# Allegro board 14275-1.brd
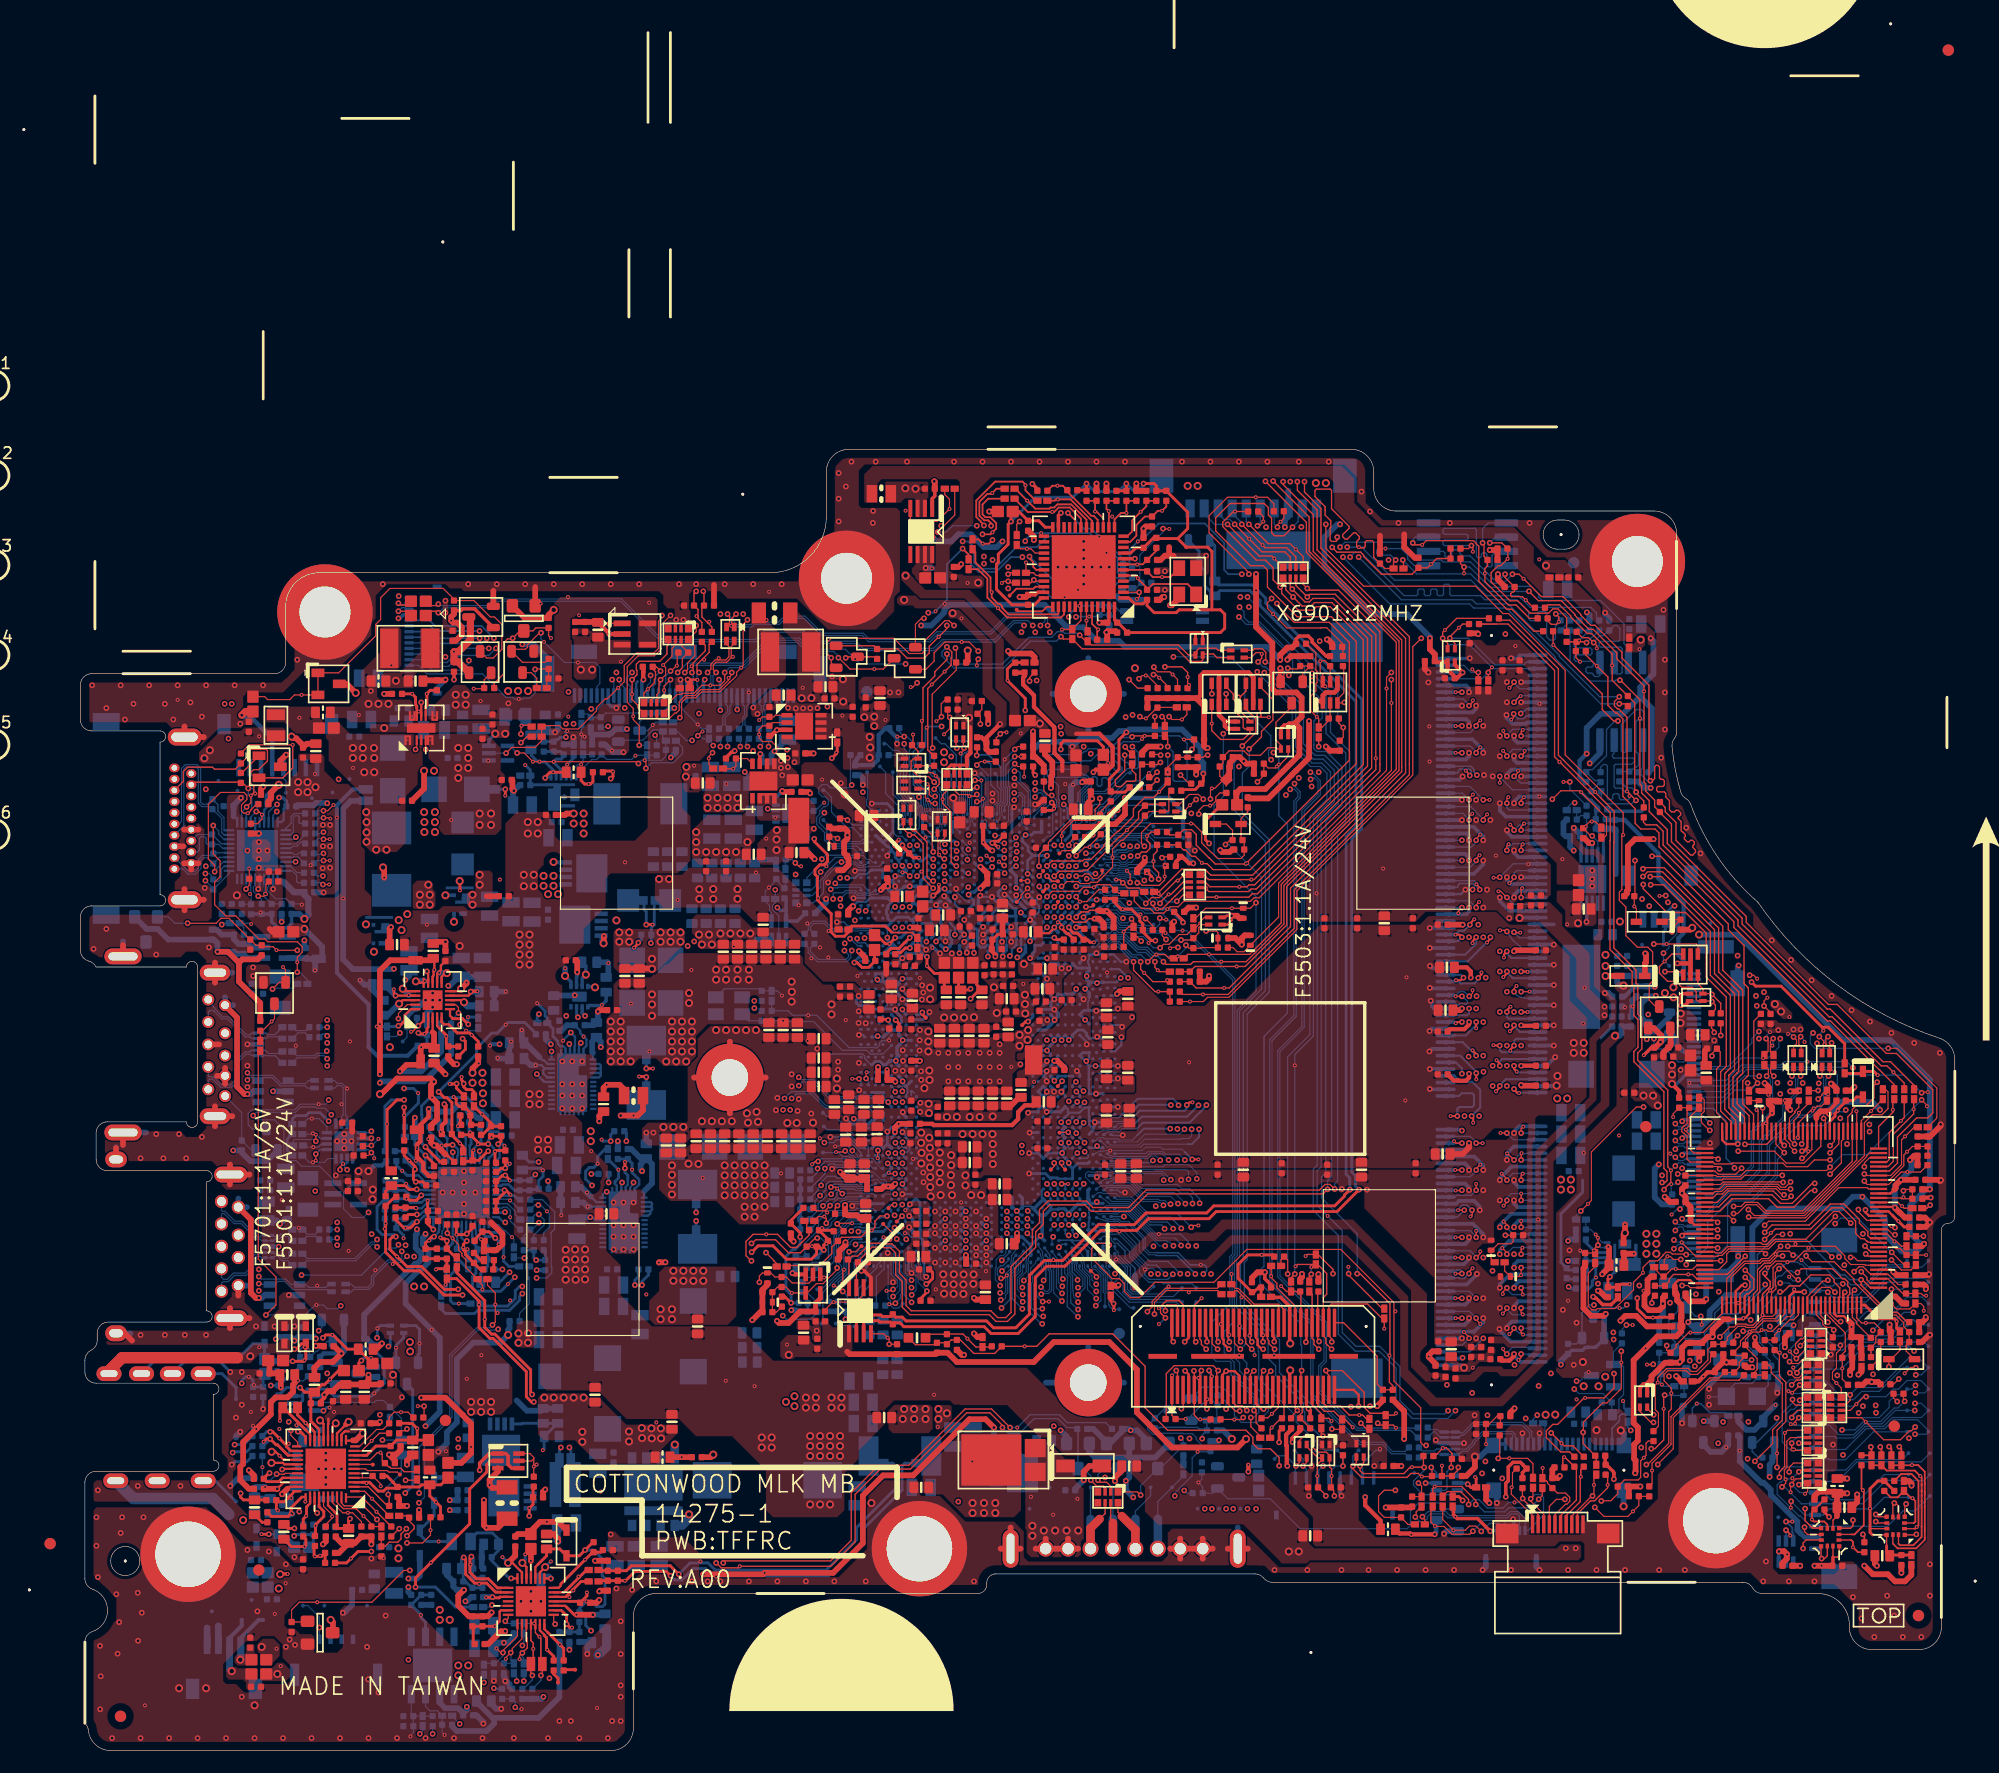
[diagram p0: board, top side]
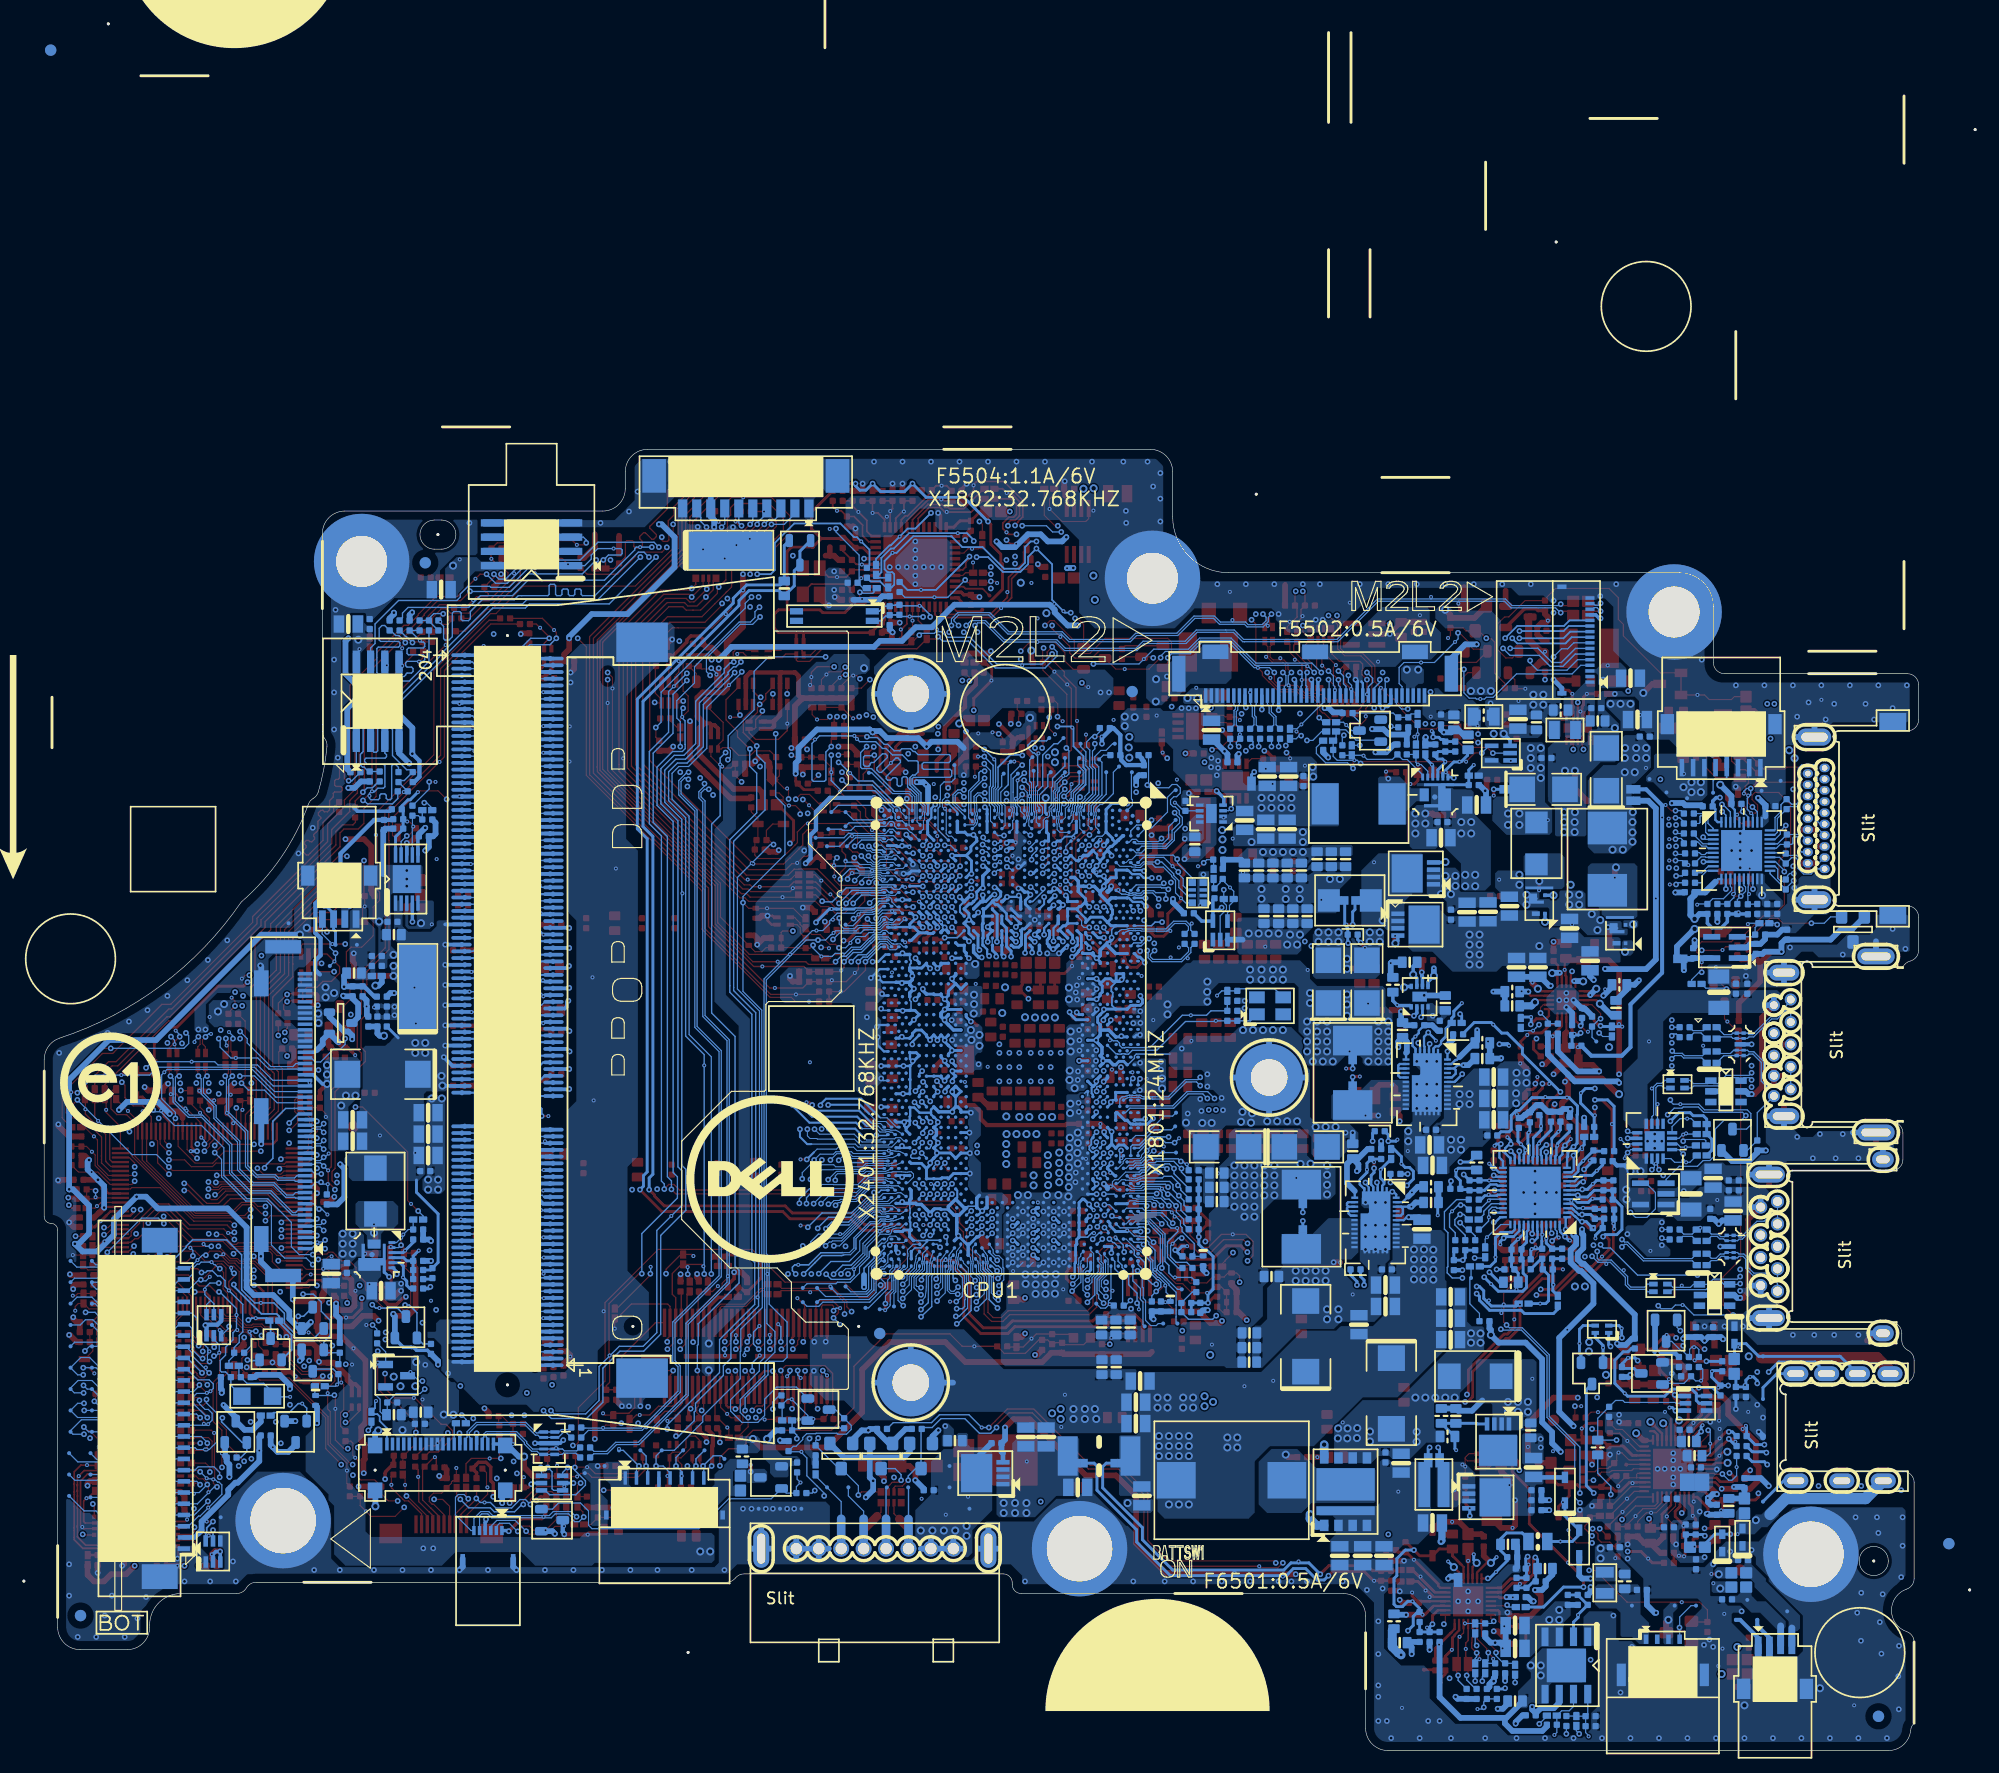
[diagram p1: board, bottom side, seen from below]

Outline 167.1 x 116 mm; copper layers: TOP, L2VCC, L3, L4, L5GND, L6, L7GND, BOTTOM. Coordinates in mm from the lower left corner of the outline.
Outline path: 0,95 0,91.9 arc(0.29,91.19) 1,90.9 7.1,90.9 arc(7.6,90.4) 7.1,89.9 7.1,76.3 arc(7.6,75.8) 7.1,75.3 1,75.3 arc(0.29,75.01) 0,74.3 0,71.35 arc(0.21,70.74) 0.75,70.38 arc(1.13,70.19) 1.4,69.85 9.45,69.85 arc(9.95,70.35) 10.45,69.85 10.45,56.05 arc(9.95,55.55) 9.45,56.05 2.4,56.05 arc(1.69,55.76) 1.4,55.05 1.4,52.7 arc(1.69,51.99) 2.4,51.7 11.25,51.7 arc(11.75,51.2) 11.25,50.7 11.25,39.2 arc(11.75,38.7) 11.25,38.2 2.5,38.2 arc(1.79,37.91) 1.5,37.2 1.5,36.58 arc(1.35,36.05) 0.95,35.68 arc(0.55,35.31) 0.4,34.79 0.4,33.75 arc(0.69,33.04) 1.4,32.75 11.85,32.75 arc(12.35,32.25) 11.85,31.75 11.85,25.9 arc(12.35,25.4) 11.85,24.9 1.4,24.9 arc(0.69,24.61) 0.4,23.9 0.4,15.34 arc(0.59,14.76) 1.07,14.39 arc(2.42,12.5) 1.07,10.61 arc(0.59,10.24) 0.4,9.66 0.4,2.44 arc(0.61,2.15) 0.71,1.81 arc(1.35,0.52) 2.7,0 47.3,0 arc(48.71,0.59) 49.3,2 49.3,12 arc(49.89,13.41) 51.3,14 80,14 arc(80.57,14.23) 80.8,14.8 80.8,14.95 arc(81.03,15.52) 81.6,15.75 104.71,15.75 arc(105.14,15.65) 105.49,15.37 arc(105.84,15.1) 106.27,15 148.21,15 arc(148.71,14.87) 149.07,14.5 arc(149.44,14.13) 149.94,14 154.9,14 arc(156.88,13.18) 157.7,11.2 157.7,11 arc(158.29,9.59) 159.7,9 163.9,9 arc(165.31,9.59) 165.9,11 165.9,46.4 arc(166.08,46.82) 166.5,47 arc(166.92,47.18) 167.1,47.6 167.1,61.61 arc(166.72,62.78) 165.72,63.51 arc(156.64,68.24) 149.55,75.63 arc(145.99,79.61) 143.55,84.36 arc(143.38,84.66) 143.12,84.88 arc(142.84,85.13) 142.67,85.46 arc(142.18,87.47) 141.89,89.52 arc(141.93,89.89) 142.1,90.23 arc(142.26,90.53) 142.31,90.87 arc(142.3,91.18) 142.3,91.5 142.3,108.5 arc(141.71,109.91) 140.3,110.5 117.3,110.5 arc(115.89,111.09) 115.3,112.5 115.3,114 arc(114.71,115.41) 113.3,116 68.5,116 arc(67.09,115.41) 66.5,114 66.5,110 arc(65.04,106.46) 61.5,105 21.3,105 arc(19.18,104.12) 18.3,102 18.3,97 arc(18.01,96.29) 17.3,96 1,96 arc(0.29,95.71) 0,95 ; 2.7,16.9 arc(4,18.2) 5.3,16.9 arc(4,15.6) 2.7,16.9 ; 6.7,17.5 arc(9.6,20.4) 12.5,17.5 arc(9.6,14.6) 6.7,17.5 ; 19.55,101.5 arc(21.8,103.75) 24.05,101.5 arc(21.8,99.25) 19.55,101.5 ; 56.3,60 arc(57.9,61.6) 59.5,60 arc(57.9,58.4) 56.3,60 ; 66.05,104.5 arc(68.3,106.75) 70.55,104.5 arc(68.3,102.25) 66.05,104.5 ; 71.9,18 arc(74.8,20.9) 77.7,18 arc(74.8,15.1) 71.9,18 ; 88.25,94.2 arc(89.85,95.8) 91.45,94.2 arc(89.85,92.6) 88.25,94.2 ; 88.25,32.8 arc(89.85,34.4) 91.45,32.8 arc(89.85,31.2) 88.25,32.8 ; 131.7,109.7 132.3,109.7 arc(133.6,108.4) 132.3,107.1 131.7,107.1 arc(130.4,108.4) 131.7,109.7 ; 136.55,106 arc(138.8,108.25) 141.05,106 arc(138.8,103.75) 136.55,106 ; 142.9,20.5 arc(145.8,23.4) 148.7,20.5 arc(145.8,17.6) 142.9,20.5

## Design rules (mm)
constraint set DEFAULT: min track width 0.127, pair gap 0.102
net group BOOST_MON: nets BOOST_MON I_BATT
net group CLK_PCI_LPC: nets CLK_PCI_LPC PCI_CLK_LPC0
net group CLK_PCI_LPC_MEC: nets CLK_PCI_LPC_MEC PCI_CLK_LPC1
net group DDR3_A_ODT10-MW: nets M_A_DIMA_ODT0 M_A_DIMA_ODT1
net group EDP_AUX: nets EDP_AUX EDP_AUX_DP
net group EDP_AUX#: nets EDP_AUX# EDP_AUX_DN
net group EDP_TX0: nets EDP_TX0 EDP_TX0_DP
net group EDP_TX0#: nets EDP_TX0# EDP_TX0_DN
net group EDP_TX1: nets EDP_TX1 EDP_TX1_DP
net group EDP_TX1#: nets EDP_TX1# EDP_TX1_DN
net group FAN_TACH: nets FAN_TACH1 FAN_TACH1_C
net group GND: nets EC_AGND MIC_GND
net group HDA_CODEC_RST#: nets HDA_CODEC_RST# HDA_RST#
net group HDA_CODEC_SDIN0: nets HDA_CODEC_SDIN0 HDA_SDIN0
net group HDA_CODEC_SYNC: nets HDA_CODEC_SYNC HDA_SYNC
net group I_SYS: nets I_SYS P_SYS
net group LCD_TST: nets LCD_TST LCD_TST_EN
net group LPC_LAD0: nets LPC_LAD0 LPC_LAD0_R
net group LPC_LAD1: nets LPC_LAD1 LPC_LAD1_R
net group LPC_LAD2: nets LPC_LAD2 LPC_LAD2_R
net group LPC_LAD3: nets LPC_LAD3 LPC_LAD3_R
net group LPC_LFRAME#: nets LPC_LFRAME# LPC_LFRAME#_R
net group PCIE_RX_CPU5-DIFF190: nets PCIE_RX_CPU_N5 PCIE_RX_CPU_P5
net group PCIE_TX_CPU_N5: nets PCIE_TX_CPU_N5 PCIE_TX_WLAN_N5
net group PCIE_TX_CPU_P5: nets PCIE_TX_CPU_P5 PCIE_TX_WLAN_P5
net group PWR_VCCGT_VSP: nets PWR_VCCGT_VSP VCCGT_SENSE
net group SPI_CLK_CPU: nets SPI_CLK_CPU SPI_CLK_ROM
net group SPI_CS_CPU_N0: nets SPI_CS_CPU_N0 SPI_CS_ROM_N0
net group SPI_HOLD_CPU: nets SPI_HOLD_CPU SPI_HOLD_ROM
net group SPI_SI_CPU: nets SPI_SI_CPU SPI_SI_ROM
net group SPI_SO_CPU: nets SPI_SO_CPU SPI_SO_ROM
net group SPI_WP_CPU: nets SPI_WP_CPU SPI_WP_ROM
net group USB20_DN0_C: nets USB20_DN0_C USB_PN0_R
net group USB20_DN1_C: nets USB20_DN1_C USB_CPU_PN1
net group USB20_DP0_C: nets USB20_DP0_C USB_PP0_R
net group USB20_DP1_C: nets USB20_DP1_C USB_CPU_PP1
net group USB30_RXDN1_C: nets USB30_RX_CPU_N1 USB30_RXDN1_C
net group USB30_RXDN2_C: nets USB30_RX_CPU_N2 USB30_RXDN2_C
net group USB30_RXDP1_C: nets USB30_RX_CPU_P1 USB30_RXDP1_C
net group USB30_RXDP2_C: nets USB30_RX_CPU_P2 USB30_RXDP2_C
net group USB_3+: nets USB_3+ USB_CPU_PP3
net group USB_3-: nets USB_3- USB_CPU_PN3
net group USB_CAMERA_N: nets USB_CAMERA_N USB_CPU_PN4
net group USB_CAMERA_P: nets USB_CAMERA_P USB_CPU_PP4
net group USB_CPU0-DIFF0: nets USB_CPU_PN0 USB_CPU_PP0
net group USB_CPU_PN2: nets USB_CPU_PN2 USB_CPU_PN2_C
net group USB_CPU_PN5: nets USB_CPU_PN5 USB_CPU_PN5_C
net group USB_CPU_PN6: nets USB_CPU_PN6 USB_PN6_TPNL
net group USB_CPU_PN7: nets USB_CPU_PN7 USB_CPU_PN7_C
net group USB_CPU_PP2: nets USB_CPU_PP2 USB_CPU_PP2_C
net group USB_CPU_PP5: nets USB_CPU_PP5 USB_CPU_PP5_C
net group USB_CPU_PP6: nets USB_CPU_PP6 USB_PP6_TPNL
net group USB_CPU_PP7: nets USB_CPU_PP7 USB_CPU_PP7_C
net group XTAL_48: nets RTC_X1 RTC_X2
net group AUDIO_20MIL: nets RING2 RING2_R RING2_R_C SLEEVE SLEEVE_R SLEEVE_R_C
net group AUDIO_BEEP_10MIL: nets AUD_HP1_JACK_L AUD_HP1_JACK_L1 AUD_HP1_JACK_R AUD_HP1_JACK_R1 AUD_PC_BEEP AUD_PC_BEEP_C AUD_PC_BEEP_R AUD_PORTA_L_R_B AUD_PORTA_R_R_B AUD_SENSE_A BEEP CBN CBP HDA_SPKR_R KBC_BEEP_R LINE1-L_C LINE1-L_R LINE1_L LINE1_R MICBIASB SENSE_PORTA SLEEVE_CTRL SPKR
net group AUDIO_OTHER_4MIL: nets CP_VNEG CP_VPOS LDO_AVDD LDO_VDD_CORE N18046859 VREFP
net group CFG_50-MW: nets CFG0 CFG1 CFG2 CFG3 CFG4 CFG5 CFG6 CFG7 CFG8 CFG9 CFG10 CFG11 CFG12 CFG13 CFG14 CFG15 CFG16 CFG17 CFG18 CFG19
net group CLK_50-MWS: nets SUSACK#_R SUSCLK SUSCLK_R
net group CODEC_BITCLK_R: nets CODEC_BITCLK_R HDA_BITCLK HDA_CODEC_BITCLK
net group CODEC_SDOUT_R: nets CODEC_SDOUT_R HDA_CODEC_SDOUT HDA_SDOUT
net group COMP_20MIL: nets CFG_RCOMP CPU_POPIRCOMP CSI2_COMP EDP_COMP EMMC_RCOMP PCH_POPIRCOMP SD_RCOMP SM_RCOMP_0 SM_RCOMP_1 SM_RCOMP_2 USBCOMP XCLK_BIASREF
net group CPU_50-MWS: nets CMP_VOUT1 H_PROCHOT# H_PROCHOT#_EC H_PROCHOT#_R PWR_CHG_PROCHOT#
net group DDR3_A_CMD_40-MW: nets M_A_A0 M_A_A1 M_A_A2 M_A_A3 M_A_A4 M_A_A5 M_A_A6 M_A_A7 M_A_A8 M_A_A9 M_A_A10 M_A_A11 M_A_A12 M_A_A13 M_A_A14 M_A_A15 M_A_BS0 M_A_BS1 M_A_BS2 M_A_CAS# M_A_RAS# M_A_WE#
net group DDR3_A_DATA_00_50-MW: nets M_A_DQ0 M_A_DQ1 M_A_DQ2 M_A_DQ3 M_A_DQ4 M_A_DQ5 M_A_DQ6 M_A_DQ7
net group DDR3_A_DATA_01_50-MW: nets M_A_DQ8 M_A_DQ9 M_A_DQ10 M_A_DQ11 M_A_DQ12 M_A_DQ13 M_A_DQ14 M_A_DQ15
net group DDR3_A_DATA_02_50-MW: nets M_A_DQ16 M_A_DQ17 M_A_DQ18 M_A_DQ19 M_A_DQ20 M_A_DQ21 M_A_DQ22 M_A_DQ23
net group DDR3_A_DATA_03_50-MW: nets M_A_DQ24 M_A_DQ25 M_A_DQ26 M_A_DQ27 M_A_DQ28 M_A_DQ29 M_A_DQ30 M_A_DQ31
net group DDR3_A_DATA_04_50-MW: nets M_A_DQ32 M_A_DQ33 M_A_DQ34 M_A_DQ35 M_A_DQ36 M_A_DQ37 M_A_DQ38 M_A_DQ39
net group DDR3_A_DATA_05_50-MW: nets M_A_DQ40 M_A_DQ41 M_A_DQ42 M_A_DQ43 M_A_DQ44 M_A_DQ45 M_A_DQ46 M_A_DQ47
net group DDR3_A_DATA_06_50-MW: nets M_A_DQ48 M_A_DQ49 M_A_DQ50 M_A_DQ51 M_A_DQ52 M_A_DQ53 M_A_DQ54 M_A_DQ55
net group DDR3_A_DATA_07_50-MW: nets M_A_DQ56 M_A_DQ57 M_A_DQ58 M_A_DQ59 M_A_DQ60 M_A_DQ61 M_A_DQ62 M_A_DQ63
net group DDR3_CKE_40-MW: nets M_A_CKE0 M_A_CKE1 M_A_CS#0 M_A_CS#1
net group JTAG-MW: nets EC5048_TX PCH_JTAG_TCK PCH_JTAG_TDI PCH_JTAG_TDO PCH_JTAG_TMS
net group KB: nets KSI0 KSI1 KSI2 KSI3 KSI4 KSI5 KSI6 KSI7 KSO0 KSO1 KSO2 KSO3 KSO4 KSO5 KSO6 KSO7 KSO8 KSO9 KSO10 KSO11 KSO12 KSO13 KSO14 KSO15 KSO16
net group LCD_BKLT: nets BKLT_CTRL L_BKLT_CTRL LCD_BRIGHTNESS
net group LED: nets BAT1_LED# BAT2_LED# BATT_WHITE_LED# CAP_LED# CAP_LED_R# CHG_AMBER_LED#
net group LED_20MIL: nets CAP_LED CAP_LED#_R CAP_LED_Q
net group LPC-MW: nets LPC_FRAME#_DEBUG LPC_LAD0_C LPC_LAD1_C LPC_LAD2_C LPC_LAD3_C SERIRQ
net group OTHER_4MIL-MWS: nets +3VLP A5_TP A67_TP A70_TP AC_PRESENT AD+_G_1 AD_IA ALS_INT# ALS_INT#_HUB AUX_EN_WOWL AV1_TP AV71_TP B71_TP BA1_TP BA2_TP BA71_TP BB67_TP BB70_TP BKLGT_PWM BLON_OUT BLON_OUT_C BOARD_ID BT_RADIO_DIS# C1_TP CAM_MIC_CBL_DET# CFG CLKREQ_PCIE#1 CLKREQ_PCIE#2 CLKREQ_PCIE#3 CLKREQ_PCIE#4 CLKREQ_PCIE#5 CLKREQ_PEG#0 CLKRUN# CLKRUN#_R CPU_DP1_HPD CTL1 CTL2 CTL3 DBC_EN_R DBC_PANEL_EN DCIN_EN DDCBUF DDR0_PAR DDR1_PAR E51_TXD_R E71_TP EAPD# EC_MUTE# EC_WAKE# EDP_DISP_UTIL EDP_HPD EDP_HPD_CONN EQ FAN1_PWM FAN_PWM1_C GPD2/LAN_WAKE# GPD11/LANPHYPC GPP_B2/VRALERT# GPP_B4/CPU_GP3 GPP_B18/GSPI0_MOSI GPP_B22 GPP_B23/SML1ALERT# GPP_C2/SMBALERT# GPP_C5/SML0ALERT# GPP_E0/SATAXPCIE0/SATAGP0 GPP_E1/SATAXPCIE1/SATAGP1 GPP_E2/SATAXPCIE2/SATAGP2 GPP_E3/CPU_GP0 H_CATERR# HDD_DEVSLP HDD_DEVSLP_R HDD_EN_PCH HDMI_EC_DET# HDMI_EC_DET#_C HOME_BTN# HOME_BTN#_C HOST_DEBUG_TX HPD_HDMI_CON HPD_HDMI_CON_C HSIOPC_R HSYNC_LCD HSYNC_R HSYNC_TPNL I_ADP ICSP_CLK_R ICSP_CLR ICSP_DATA_R ICSP_MCLR_R ILIM_HI ILIM_LO ILIM_SEL INT_TP# ISET ITP_PMODE JTAG_CLK JTAG_PU JTAG_RST# JTAG_TDO KB_CLOSE#_2 KB_DISABLE KB_DISABLE_HUB KBC_PWRBTN# L_BKLT_EN L_BKLT_EN_EC LCD_TST_C LID_CL_SIO# ME_FWP_EC MSM# MUTE_CTRL PANEL_SIZE1 PBAT_PRES1# PBAT_PRES# PCH_ALW_ON PCH_BATLOW# PCH_PLTRST#_EC PCH_THERMTRIP# PCH_WAKE# PIRQA# PLT_RST# PME# POWER_SW_IN# PRE PROC_SELECT# PS_ID PS_ID_R2 PSYS PWR_5V_VCLK PWR_CHG_ACOK PWR_CHG_IADP PWR_CHG_IBAT PWR_CHG_PMON RESET_OUT# REXT RTC_DET# SA0_DIMA SA1_DIMA SATA_ACT# SIO_EXT_SCI# SIO_EXT_SCI#_R SIO_EXT_SMI# SIO_EXT_SMI#_R SIO_PWRBTN# SKTOCC# SM_INTRUDER# SPDIF_TP SPKR_MUTE_TP SYS_PRES1# TOUCHPAD_INTR# TP_EN# TP_PMODE_XDP_RST_R_N U4006_CT USB_OC0# USB_OC1# USB_OC2# USB_OC3# USB_UART_SEL_D9 USBCHARGER_CB0 USBDET_CON# USBDET_CON#_R VCREF0 VOL_DOWN# VOL_UP# VR_EN VR_RDY WIFI_RF_EN ZVM#
net group PEC_50-MWS: nets H_PECI PCH_PLTRST# PECI_EC
net group PLATFORM-MWS: nets 1D0V_S5_PWRGD 1D8S_EN# 1D8S_EN_R# 1D8V_S5_PWROK 1D35V_VTT_PWRGD 3V5V_S0_ON 3V_5V_EN 3V_5V_POK 3V_5V_POK# 3V_5V_POK_C ALL_SYS_PWRGD ALWON DDR3_DRAMRST# DS3_PWRCTL EDP_VDD_EN EXT_PWR_GATE# FIVR_EN_R H_CPUPWRGD H_VCCST_PWRGD LVDS_VDD_EN_R ME_SUS_PWR_ACK ME_SUS_PWR_ACK_R PCH_DPWROK PCH_RSMRST# PLT_RST#_DEBUG PM_PCH_PWROK PM_RSMRST# PM_RSMRST#_M PM_RSMRST#_R PM_RSMRST_PWRGD_XDP PTP_DIS# PTP_INT#_EC PU4902_S5 PWR_1D0V_EN PWR_1D0V_PG PWR_1D5V_EN PWR_1D8V_EN PWR_1D8V_POK PWR_1D35V_EN PWR_1D35V_PGOOD PWR_VCORE_EN RISING TIME2 RSMRST_PWRGD# RTC_RST# RTCRST_ON RUNPWROK SIO_EXT_WAKE# SIO_SLP_A# SIO_SLP_S3# SIO_SLP_S4# SIO_SLP_S5# SIO_SLP_SUS# SLP_LAN# SM_DRAMRST# SM_PGCNTL SRTC_RST# SUS_STAT#/LPCPD# SUSACK# SYS_PWROK TOUCH_PANEL_INTR# TP_ON#_GATE USB_CHG_EN USB_EN# USB_PWR_EN# VCCSTG_EN_R VCCSTU_EN VCCSTU_EN_R VTT_EN
net group POWER_10M: nets 1.8V_RUN_FB 3D3V_GSEN2 3D3V_MCU 3V5V_CT1 3V5V_CT2 +1.8V +V1.00A_XDP +VCCCLK2 +VCCCLK4 +VCCCLK5 +VCCCOREG0 +VCCCOREG1 +VCCDSW_1P0 +VCCFUSEPRG +VCCPAZIO +VCCPDSW_3P3 +VCCPRTC_3P3 +VCCSTG +VDD18 ACAV_IN ACOK_IN AD+_G_2 AVDD5V FAN1_TACH N78881610 PU4902_VCNTL PWR_1D0V_BOOT_A PWR_1D0V_FB_A PWR_1D0V_ILIMT PWR_1D35V_BYP PWR_1D35V_C_R PWR_1D35V_IMAX PWR_1D35V_LDO_P5 PWR_1D35V_VFB PWR_3D3V_CS2 PWR_3D3V_FEEDBACK PWR_3D3V_VFB2 PWR_5V_CS1 PWR_5V_VFB1 PWR_CHG_CELL PWR_CHG_CMPIN_1 PWR_CHG_CMPOUT_1 PWR_CHG_ILIM PWR_VCCGT_COMP PWR_VCCGT_COMP_R PWR_VCCGT_CSCOMP PWR_VCCGT_CSNA PWR_VCCGT_CSP1 PWR_VCCGT_CSP2 PWR_VCCGT_CSPA PWR_VCCGT_CSREF PWR_VCCGT_CSSUM PWR_VCCGT_DIFFOUT PWR_VCCGT_DISB#A PWR_VCCGT_FB PWR_VCCGT_FB_R PWR_VCCGT_GLA PWR_VCCGT_ICCMAX PWR_VCCGT_ILIM PWR_VCCGT_ILIM_NTC PWR_VCCGT_IOUT PWR_VCCGT_NTC PWR_VCCGT_PWMA PWR_VCCGT_PWMB PWR_VCCGT_TSENSE PWR_VCCGT_VCCA PWR_VCCGT_VSN PWR_VCCGT_VSN_R PWR_VCCSA_COMP PWR_VCCSA_COMP_L PWR_VCCSA_COMP_R PWR_VCCSA_CSN PWR_VCCSA_CSN_NTC PWR_VCCSA_CSP PWR_VCCSA_CSP1B PWR_VCCSA_ICCMAX PWR_VCCSA_ILIM PWR_VCCSA_IOUT PWR_VCCSA_VSN PWR_VCCSA_VSN_R PWR_VCCSA_VSP PWR_VCCSA_VSP_R PWR_VCORE_COMP PWR_VCORE_COMP_R PWR_VCORE_CSN PWR_VCORE_CSNNTC PWR_VCORE_CSP PWR_VCORE_CSP_1A PWR_VCORE_DISB# PWR_VCORE_DRVON PWR_VCORE_ICCMAX PWR_VCORE_ILIM PWR_VCORE_IOUT PWR_VCORE_NTC PWR_VCORE_ROSC_COREGT PWR_VCORE_ROSC_SAUS PWR_VCORE_TSENSE PWR_VCORE_VR_RDY PWR_VCORE_VRHOT# PWR_VCORE_VRMP PWR_VCORE_VSN PWR_VCORE_VSN_R PWR_VCORE_VSP PWR_VCORE_VSP_L PWR_VCORE_VSP_R Q6204_G V0.85A_VID0 V0.85A_VID1 VCCRTCEXT VDD_HDA VDD_IO
net group POWER_10M_POWER: nets PWR_1D0V_BOOT PWR_1D0V_BYP PWR_1D0V_FB PWR_1D0V_LDO PWR_3D3V_EN2 PWR_5V_EN1 PWR_CHG_1 PWR_CHG_ACDET PWR_CHG_CMPIN PWR_CHG_CMPOUT PWR_CHG_REGN PWR_CHG_SRN_R PWR_CHG_SRP_R PWR_CHG_VCC PWR_VCORE_ADDR_BOOT PWR_VCORE_GL VSS_AY71
net group POWER_15M: nets Q6205_Q
net group POWER_20M: nets 3D3V_AUX_KBC_33 3D3V_AUX_KBC_R 3D3V_AUX_S5 3D3V_RUN_FFS 5V_AUX_S5 +RTC_VCC +V_VREF_PATH1 +V_VREF_PATH3 DC_IN_D EC_VTT ECVBAT FALL_INT2 PWR_1D35V_BOOT PWR_1D35V_BOOT_R PWR_3D3V_VBST2 PWR_3D3V_VBST2_1 PWR_5V3D3V_VREG3 PWR_5V3D3V_VREG5 PWR_5V_FEEDBACK PWR_5V_VBST1 PWR_5V_VBST1_1 PWR_5V_VO1 PWR_CHG_BTST PWR_CHG_BTST1 PWR_CHG_PHASE_R PWR_CPUCORE_SNUB PWR_VCORE_VCCA RTC_AUX_S5
net group POWER_20M_POWER: nets BATDRV# PWR_CHG_BAT PWR_CHG_CMSRC PWR_VCCGT_BOOTA PWR_VCCGT_BOOTA_RC PWR_VCCGT_PHASEDA PWR_VCCSA_BST PWR_VCCSA_BST_RC PWR_VCCSA_PWM PWR_VCORE_BOOT PWR_VCORE_BOOT_RC PWR_VCORE_PHASED PWR_VCORE_PWM PWR_VCORE_VCC
net group POWER_25M: nets PQ3802_1 PS_ID_R PSID_DISABLE#_R_C
net group POWER_40M_POWER: nets 1D5V_PWR PWR_3D3V_DRVH2 PWR_3D3V_DRVL2 PWR_CHG_BATDRV PWR_CHG_HIDRV PWR_CHG_LODRV PWR_VCCSA_DRVH PWR_VCCSA_DRVL
net group PSID_4.5MIL: nets PSID
net group REF_10M: nets VR_CAP
net group SATA_RXN0_R: nets SATA_RX_CPU_N0
net group SATA_RXP0_R: nets SATA_RX_CPU_P0
net group SATA_TXN0_R: nets SATA_TX_CPU_N0
net group SATA_TXP0_R: nets SATA_TX_CPU_P0
net group SENSE_VGT-DIFF: nets VSSGT_SENSE
net group SENSOR: nets FFS_INT1_D FFS_INT2 FFS_INT2_D FFS_INT2_Q FFS_INT2_Q_R FFS_SDO GSEN2_INT1 GSEN2_INT1_C GSEN2_INT1_C_HUB GSEN2_INT2 GSEN2_INT2_C GSEN2_INT2_C_HUB GSEN_INT1 GSEN_INT1_HUB GSEN_INT2 GSEN_INT2_HUB GSENSOR_CS GSENSOR_SDO GYRO_DRDY GYRO_DRDY_HUB GYRO_INT GYRO_INT_C GYRO_INT_C_HUB GYRO_INT_P11 HDD_FALL_INT HUB_PA1 HUB_PA2 HUB_PA3 HUB_PA4 HUB_PA5 HUB_PA6 INT2_SELECT MCU_BOOT0 MCU_OSCI MCU_OSCO MCU_RST# SWCLK SWDIO USBDISABLE
net group SMBUS_50-MWS: nets CLK_TP_SIO DAT_TP_SIO DDC_CLK_HDMI DDC_CLK_PH1 DDC_DATA_HDMI DDC_DATA_PH2 DMIC_CLK DMIC_CLK_R DMIC_DATA DMIC_DATA_R I2C0_SCL I2C0_SCL_R I2C0_SCL_TCH_PAD I2C0_SDA I2C0_SDA_R I2C0_SDA_TCH_PAD I2C1_SCL I2C1_SDA ICSP_CLOCK ICSP_DATA PBAT_SMBCLK1 PBAT_SMBDAT1 PCH_SMBCLK PCH_SMBDATA SENSOR_I2C_SCL SENSOR_I2C_SCL_2G SENSOR_I2C_SCL_HUB SENSOR_I2C_SDA SENSOR_I2C_SDA_2G SENSOR_I2C_SDA_HUB SMBCLK1 SMBCLK2 SMBDA1 SMBDA2 SML0_SMBCLK SML0_SMBDATA SML1_SMBCLK SML1_SMBDATA THM_SML1_CLK THM_SML1_DATA TPCLK_C TPDATA_C VR_SVID_CLK VR_SVID_DATA XDP_SMBCLK XDP_SMBDAT
net group SPI_50-MW: nets EC_SPI_CLK EC_SPI_CS0# EC_SPI_MISO EC_SPI_MOSI SIO_RCIN# SPI1_CLK_ROM_R SPI1_HOLD_ROM_R SPI1_SI_ROM_R SPI1_SO_ROM_R SPI1_WP_ROM_R SPI_CLK_ROM_EC SPI_CLK_ROM_R SPI_CS_CPU_N1 SPI_CS_ROM_N1 SPI_HOLD_ROM_R SPI_SI_ROM_EC SPI_SI_ROM_R SPI_SO_ROM_EC SPI_SO_ROM_R SPI_WP_ROM_R
net group SVID-MW: nets H_CPU_SVIDALRT# H_CPU_SVIDCLK H_CPU_SVIDDAT PWR_VCORE_ALERT# PWR_VCORE_SCLK PWR_VCORE_SDIO VR_SVID_ALERT#
net group T8-MW: nets CMP_VIN0 CMP_VIN0_R CMP_VOUT0 VD_IN1_C
net group TESTPD_4MIL: nets CPU_A16_TP CPU_D1_TP CPU_D4_TP CPU_D5_TP CPU_D6_TP RSVD_F65 RSVD_G65 RSVD_TP_AK12 RSVD_TP_AK13 RSVD_TP_AW70 RSVD_TP_AW71 RSVD_TP_BA68 RSVD_TP_BA70 RSVD_TP_BB68 RSVD_TP_BB69 TP1_AY4 TP2_BB3 TP4_BB5 TP5_AU5 TP6_AT5
net group THERM_SHUTDOWN: nets ALERT# PURE_HW_SHUTDOWN# T_CRIT# THERM_SYS_SHDN#
net group UART_MW-MW: nets LPSS_UART2_CTS# LPSS_UART2_RXD LPSS_UART2_TXD UART0_CTS# UART0_RTS# UART0_RXD UART0_TXD UART1_CTS# UART1_RTS# UART1_RXD
net group USB30_TXDN1_C: nets USB30_TX_CPU_N1 USB30_TXDN1_C USB30_TXDN1_R
net group USB30_TXDN2_C: nets USB30_TX_CPU_N2 USB30_TXDN2_C USB30_TXDN2_R
net group USB30_TXDP1_C: nets USB30_TX_CPU_P1 USB30_TXDP1_C USB30_TXDP1_R
net group USB30_TXDP2_C: nets USB30_TX_CPU_P2 USB30_TXDP2_C USB30_TXDP2_R
net group XDP-MW: nets BP_PWRGD_RST# SPI0_MOSI_XDP XDP_DBRESET# XDP_DBRESET_XDP# XDP_PRSNT_PIN1 XDP_SPI0_IO2 XDP_TMS
net group XDP_BPM-MW: nets XDP_BPM0 XDP_BPM1 XDP_BPM2 XDP_BPM3
net group XDP_TCLK-MWS: nets XDP_TCK_JTAGX XDP_TCLK XDP_TCLK1
net group XDP_TRST-MWS: nets XDP_PRDY# XDP_PREQ# XDP_TDI XDP_TDO_CPU XDP_TRST#
net group XTAL-MW: nets XTAL1 XTAL2 XTAL24_IN XTAL24_OUT XTAL24_OUT_R XTAL_KBC_2

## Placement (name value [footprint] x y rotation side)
AFTP2601  AFTE14P-GP  [AFTE14P-75]  141.13 71.83 180 bottom
AFTP2602  AFTE14P-GP  [AFTE14P-75]  141.64 69.94 180 bottom
AFTP2603  AFTE14P-GP  [AFTE14P-75]  139.22 71.83 180 bottom
AFTP2604  AFTE14P-GP  [AFTE14P-75]  145.32 73.75 180 bottom
AFTP2901  AFTE14P-GP  [AFTE14P-75]  11.72 12.41 180 bottom
AFTP2902  AFTE14P-GP  [AFTE14P-75]  15.27 13.43 180 bottom
AFTP2903  AFTE14P-GP  [AFTE14P-75]  14.38 11.65 180 bottom
AFTP2904  AFTE14P-GP  [AFTE14P-75]  16.29 11.65 180 bottom
AFTP2906  AFTE14P-GP  [AFTE14P-75]  13.88 22.19 270 bottom
AFTP2907  AFTE14P-GP  [AFTE14P-75]  13.88 35.15 180 bottom
AFTP2908  AFTE14P-GP  [AFTE14P-75]  13.88 27.91 270 bottom
AFTP2910  AFTE14P-GP  [AFTE14P-75]  13.88 31.34 180 bottom
AFTP4301  AFTE14P-GP  [AFTE14P-75]  12.3 86.45 180 bottom
AFTP4302  AFTE14P-GP  [AFTE14P-75]  14 85.57 180 bottom
AFTP4303  AFTE14P-GP  [AFTE14P-75]  22.48 85.42 180 bottom
AFTP4304  AFTE14P-GP  [AFTE14P-75]  20.64 84.9 180 bottom
AFTP4305  AFTE14P-GP  [AFTE14P-75]  18.32 85.39 180 bottom
AFTP4306  AFTE14P-GP  [AFTE14P-75]  95.41 23.46 180 bottom
AFTP4307  AFTE14P-GP  [AFTE14P-75]  91.98 23.46 180 bottom
AFTP4308  AFTE14P-GP  [AFTE14P-75]  90.08 23.46 180 bottom
AFTP4309  AFTE14P-GP  [AFTE14P-75]  97.31 23.46 180 bottom
AFTP4310  AFTE14P-GP  [AFTE14P-75]  86.39 25.37 180 bottom
AFTP4311  AFTE14P-GP  [AFTE14P-75]  86.39 23.46 180 bottom
AFTP4312  AFTE14P-GP  [AFTE14P-75]  84.61 21.56 180 bottom
AFTP4313  AFTE14P-GP  [AFTE14P-75]  101.51 21.56 180 bottom
AFTP4314  AFTE14P-GP  [AFTE14P-75]  103.41 21.56 180 bottom
AFTP4315  AFTE14P-GP  [AFTE14P-75]  99.6 21.56 180 bottom
AFTP4316  AFTE14P-GP  [AFTE14P-75]  23.99 86.61 180 bottom
AFTP4501  AFTE14P-GP  [AFTE14P-75]  28.73 63.21 90 bottom
AFTP6501  AFTE14P-GP  [AFTE14P-75]  162.85 43.66 180 bottom
AFTP6502  AFTE14P-GP  [AFTE14P-75]  164.75 43.66 180 bottom
AFTP6503  AFTE14P-GP  [AFTE14P-75]  164.75 41.75 180 bottom
AFTP6504  AFTE14P-GP  [AFTE14P-75]  162.85 41.75 180 bottom
AFTP6505  AFTE14P-GP  [AFTE14P-75]  164.75 39.85 180 bottom
AFTP6506  AFTE14P-GP  [AFTE14P-75]  162.85 39.85 180 bottom
AFTP6507  AFTE14P-GP  [AFTE14P-75]  164.75 37.94 180 bottom
AFTP6508  AFTE14P-GP  [AFTE14P-75]  162.85 37.94 180 bottom
AFTP6509  AFTE14P-GP  [AFTE14P-75]  164.75 36.04 180 bottom
AFTP6510  AFTE14P-GP  [AFTE14P-75]  162.85 36.04 180 bottom
AFTP6511  AFTE14P-GP  [AFTE14P-75]  164.75 34.13 180 bottom
AFTP6512  AFTE14P-GP  [AFTE14P-75]  162.85 34.13 180 bottom
AFTP6513  AFTE14P-GP  [AFTE14P-75]  164.75 32.23 180 bottom
AFTP6514  AFTE14P-GP  [AFTE14P-75]  162.85 32.23 180 bottom
AFTP6515  AFTE14P-GP  [AFTE14P-75]  162.85 30.32 180 bottom
AFTP6516  AFTE14P-GP  [AFTE14P-75]  164.75 30.32 180 bottom
AFTP6517  AFTE14P-GP  [AFTE14P-75]  164.75 28.42 180 bottom
AFTP6518  AFTE14P-GP  [AFTE14P-75]  162.85 28.42 180 bottom
AFTP6519  AFTE14P-GP  [AFTE14P-75]  162.97 26.51 180 bottom
AFTP6520  AFTE14P-GP  [AFTE14P-75]  164.88 26.51 180 bottom
AFTP6521  AFTE14P-GP  [AFTE14P-75]  162.97 24.61 180 bottom
AFTP6522  AFTE14P-GP  [AFTE14P-75]  164.88 24.61 180 bottom
AFTP6523  AFTE14P-GP  [AFTE14P-75]  162.97 22.57 180 bottom
AFTP6524  AFTE14P-GP  [AFTE14P-75]  164.88 22.7 180 bottom
AFTP6525  AFTE14P-GP  [AFTE14P-75]  150.5 23.44 180 bottom
AFTP6526  AFTE14P-GP  [AFTE14P-75]  151.37 20.8 180 bottom
AFTP6527  AFTE14P-GP  [AFTE14P-75]  118.9 24.73 180 bottom
AFTP6528  AFTE14P-GP  [AFTE14P-75]  19.84 12.92 180 bottom
AFTP6529  AFTE14P-GP  [AFTE14P-75]  25.56 12.92 180 bottom
AFTP6530  AFTE14P-GP  [AFTE14P-75]  21.75 12.92 180 bottom
AFTP6531  AFTE14P-GP  [AFTE14P-75]  117.15 25.37 180 bottom
AFTP6532  AFTE14P-GP  [AFTE14P-75]  106.46 26 180 bottom
AFTP6533  AFTE14P-GP  [AFTE14P-75]  108.24 26.76 180 bottom
AFTP6534  AFTE14P-GP  [AFTE14P-75]  113.95 26.76 180 bottom
AFTP6535  AFTE14P-GP  [AFTE14P-75]  115.86 26.76 180 bottom
AFTP6536  AFTE14P-GP  [AFTE14P-75]  112.05 26.76 180 bottom
AFTP6537  AFTE14P-GP  [AFTE14P-75]  110.14 26.76 180 bottom
BATT1  ALP-CON8-17-GP-U1  [C144KA-108A7-L-1]  93.05 18 180 bottom
C715  SC10U6D3V3MX-GP  [C603H38]  83.85 58.9 0 top
C716  SC1U10V2KX-1GP  [C402H22]  68 74.54 90 top
C717  SC1U10V2KX-1GP  [C402H22]  63.33 46.54 0 top
C718  SCD1U16V2KX-3GP  [C402H22]  91.27 71.21 180 top
C719  SC1U10V2KX-1GP  [C402H22]  87.92 66.9 270 top
C720  SCD1U16V2KX-3GP  [C402H22]  74.38 70.76 270 top
C721  SCD1U16V2KX-3GP  [C402H22]  73.95 69.94 270 top
C1101  SC1U10V2KX-1GP  [C402H22]  74.07 64.74 180 top
C1102  SC1U10V2KX-1GP  [C402H22]  74.07 61.05 180 top
C1103  SC1U10V2KX-1GP  [C402H22]  74.07 57.5 0 top
C1104  SC22U6D3V3MX-1-GP  [C603H40]  89.19 83.91 90 top
C1106  SC22U6D3V3MX-1-GP  [C603H40]  85.99 90.01 0 top
C1108  SC22U6D3V3MX-1-GP  [C603H40]  70.09 83.36 90 top
C1116  SC1U10V2KX-1GP  [C402H22]  81.64 64.08 180 top
C1117  SC1U10V2KX-1GP  [C402H22]  85.5 65.5 180 top
C1136  SC1U10V2KX-1GP  [C402H22]  76.46 54.58 180 top
C1138  SC1U10V2KX-1GP  [C402H22]  77.3 54.58 180 top
C1147  SC1U10V2KX-1GP  [C402H22]  74.96 46.07 270 top
C1148  SC1U10V2KX-1GP  [C402H22]  79.41 43.4 270 top
C1149  SC1U10V2KX-1GP  [C402H22]  79.79 50.89 180 top
C1150  SC1U10V2KX-1GP  [C402H22]  74 54.58 180 top
C1151  SC1U10V2KX-1GP  [C402H22]  82.71 68.17 270 top
C1152  SC1U10V2KX-1GP  [C402H22]  82.96 65.88 270 top
C1153  SC1U10V2KX-1GP  [C402H22]  85.63 66.77 90 top
C1154  SC1U10V2KX-1GP  [C402H22]  87.28 60.67 90 top
C1172  SC1U10V2KX-1GP  [C402H22]  78.95 74.82 90 top
C1173  SC1U10V2KX-1GP  [C402H22]  81.41 69.64 0 top
C1174  SC1U10V2KX-1GP  [C402H22]  83.04 69.64 0 top
C1175  SC1U10V2KX-1GP  [C402H22]  82.23 69.64 0 top
C1176  SC10U10V3MX-GP  [C603H36]  76.36 73.12 270 top
C1180  SC1U10V2KX-1GP  [C402H22]  78.82 73.45 90 top
C1182  SC22U6D3V3MX-1-GP  [C603H40]  63.84 80.05 90 top
C1183  SC10U10V3MX-GP  [C603H36]  82.2 74.87 0 top
C1184  SC22U6D3V3MX-1-GP  [C603H40]  76.92 74.49 270 top
C1201  SCD1U16V2KX-3GP  [C402H22]  130.21 75.79 180 top
C1202  SCD1U16V2KX-3GP  [C402H22]  127.92 75.28 270 top
C1203  SCD1U16V2KX-3GP  [C402H22]  122.08 95.6 270 top
C1204  SCD1U16V2KX-3GP  [C402H22]  123.98 35.53 180 top
C1205  SC2D2U10V3KX-1GP  [C603H36]  122.21 35.78 180 top
C1206  SCD1U16V2KX-3GP  [C402H22]  126.14 34.89 90 top
C1207  SC10U6D3V3MX-GP  [C603H38]  121.83 69.82 90 top
C1208  SC10U6D3V3MX-GP  [C603H38]  121.44 53.18 90 top
C1209  SCD1U25V3KX-GP  [C603H36]  121.7 66.01 90 top
C1210  SCD1U16V2KX-3GP  [C402H22]  121.44 73.63 90 top
C1211  SCD1U25V2KX-GP  [C402H22]  130.21 61.05 270 top
C1212  SC1U10V2KX-1GP  [C402H22]  130.21 64.61 270 top
C1213  SC1U10V2KX-1GP  [C402H22]  121.44 64.1 90 top
C1214  SC1U10V2KX-1GP  [C402H22]  126.78 96.74 0 top
C1215  SC1U10V2KX-1GP  [C402H22]  128.3 96.74 0 top
C1216  SC1U10V2KX-1GP  [C402H22]  123.86 99.15 180 top
C1218  SCD1U16V2KX-3GP  [C402H22]  129.32 75.79 180 top
C1220  SCD1U16V2KX-3GP  [C402H22]  130.21 71.34 270 top
C1221  SCD1U16V2KX-3GP  [C402H22]  121.44 60.29 90 top
C1222  SCD1U16V2KX-3GP  [C402H22]  130.21 59.28 270 top
C1601  SCD1U16V2KX-3GP  [C402H22]  65.44 72.36 0 bottom
C1602  SCD1U16V2KX-3GP  [C402H22]  64.55 72.36 0 bottom
C1701  SC220P50V2KX-3GP  [C402H22]  99.6 88.11 0 top
C1702  SCD1U16V2KX-3GP  [C402H22]  65.54 38.7 0 top
C1704  SC10U6D3V3MX-GP  [C603H38]  60.03 79.9 270 top
C1710  SCD47U10V2KX-GP  [C402H22]  112.27 89.58 0 top
C1711  SCD01U50V2KX-1GP  [C402H22]  61.25 40.86 270 top
C1717  SC10U6D3V3MX-GP  [C603H38]  55.48 86.25 270 top
C1718  SC1U10V2KX-1GP  [C402H22]  61.17 88.11 270 bottom
C1719  SC1U10V2KX-1GP  [C402H22]  57.99 88.44 270 top
C1801  SC15P50V2JN-2-GP  [C402H22]  60.74 65.5 180 bottom
C1802  SC15P50V2JN-2-GP  [C402H22]  60.74 67.28 0 bottom
C1803  SC3P50V2CN-1-GP  [C402H22]  91.73 100.78 0 bottom
C1804  SC3P50V2CN-1-GP  [C402H22]  91.73 102.46 180 bottom
C1805  SC1U10V2KX-1GP  [C402H22]  105.06 87.09 270 top
C1806  SC1U10V2KX-1GP  [C402H22]  102.29 88.56 90 top
C2101  SC1U10V2KX-1GP  [C402H22]  80.6 69.56 0 top
C2102  SC1U10V2KX-1GP  [C402H22]  79.48 72.21 180 top
C2103  SC1U10V2KX-1GP  [C402H22]  85.88 84.3 180 top
C2104  SC1U10V2KX-1GP  [C402H22]  74.71 73.75 180 top
C2105  SC1U10V2KX-1GP  [C402H22]  80.22 74.64 0 top
C2106  SC1U10V2KX-1GP  [C402H22]  81.29 77.31 270 top
C2107  SC1U10V2KX-1GP  [C402H22]  81.29 78.12 270 top
C2108  SC1U10V2KX-1GP  [C402H22]  81.69 71.44 270 top
C2109  SC1U10V2KX-1GP  [C402H22]  84.36 83.28 180 top
C2110  SCD1U16V2KX-3GP  [C402H22]  84.89 75.15 0 top
C2111  SCD1U16V2KX-3GP  [C402H22]  81.06 74.64 0 top
C2112  SCD1U16V2KX-3GP  [C402H22]  94.65 78.33 270 top
C2113  SC22U6D3V3MX-1-GP  [C603H40]  73.26 76.14 270 top
C2114  SC22U6D3V3MX-1-GP  [C603H40]  80.35 83.69 90 top
C2115  SC22U6D3V3MX-1-GP  [C603H40]  77.2 67.15 0 top
C2116  SC1U10V2KX-1GP  [C402H22]  68.79 79.75 270 top
C2117  SC1U10V2KX-1GP  [C402H22]  97.95 74.77 90 top
C2118  SCD1U16V2KX-3GP  [C402H22]  87.66 71.85 0 top
C2119  SC22U6D3V3MX-1-GP  [C603H40]  80.37 67.15 0 top
C2120  SC1U10V2KX-1GP  [C402H22]  82.68 72.76 270 top
C2121  SC1U10V2KX-1GP  [C402H22]  81.31 72.74 0 top
C2122  SC22U6D3V3MX-1-GP  [C603H40]  78.47 67.15 0 top
C2402  AZ5725-01FDR7G-GP  [SOD882-10D6-1H20]  149.64 58.39 180 top
C2403  AZ5725-01FDR7G-GP  [SOD882-10D6-1H20]  142.91 31.21 180 bottom
C2405  SC100P50V2JN-3GP  [C402H22]  141.26 40.99 0 top
C2406  SCD1U16V2KX-3GP  [C402H22]  142.65 40.73 90 top
C2408  SCD1U16V2KX-3GP  [C402H22]  147.43 34.16 0 top
C2409  SCD01U50V2KX-1GP  [C402H22]  163.79 54.3 180 top
C2410  SCD1U16V2KX-3GP  [C402H22]  142.65 48.91 270 top
C2411  SCD1U16V2KX-3GP  [C402H22]  156.55 58.39 180 top
C2412  SCD1U16V2KX-3GP  [C402H22]  163.48 47.52 90 top
C2413  SCD1U16V2KX-3GP  [C402H22]  143.54 35.91 0 top
C2414  SCD1U16V2KX-3GP  [C402H22]  163.16 42.38 90 top
C2415  SC2D2U10V3KX-1GP  [C603H36]  144.18 63.81 90 top
C2416  SCD1U16V2KX-3GP  [C402H22]  141.56 61.87 270 top
C2417  SC2D2U10V3KX-1GP  [C603H36]  144.94 60.42 180 top
C2418  SC1U10V2KX-1GP  [C402H22]  163.48 46.68 90 top
C2419  SC1U10V2KX-1GP  [C402H22]  124.86 28.23 270 top
C2420  SCD1U16V2KX-3GP  [C402H22]  144.56 35.91 0 top
C2421  SCD1U16V2KX-3GP  [C402H22]  142.02 62.68 270 top
C2422  SCD1U16V2KX-3GP  [C402H22]  152.8 37.21 270 top
C2423  SCD1U16V2KX-3GP  [C402H22]  150.53 58.34 180 top
C2424  SC10P50V2JN-4GP  [C402H22]  149.13 33.29 270 bottom
C2425  SC10P50V2JN-4GP  [C402H22]  150.91 33.29 90 bottom
C2426  SC1U10V2KX-1GP  [C402H22]  160.94 37.31 90 top
C2427  SC2200P50V2KX-2GP  [C402H22]  148.88 36.16 90 top
C2428  SCD1U16V2KX-3GP  [C402H22]  157.89 36.42 0 top
C2429  SCD1U16V2KX-3GP  [C402H22]  164.03 50.88 90 top
C2435  SC2200P50V2KX-2GP  [C402H22]  146.46 35.78 0 top
C2441  SC2200P50V2KX-2GP  [C402H22]  150.15 36.15 0 top
C2501  SC10U10V5KX-2GP  [C805H54]  131.71 103.5 270 bottom
C2502  SCD1U16V2KX-3GP  [C402H22]  133.09 104.58 90 top
C2503  SCD47U10V2KX-GP  [C402H22]  139.61 67.68 0 bottom
C2504  SCD1U16V2KX-3GP  [C402H22]  138.08 100.42 0 bottom
C2505  SC10U10V5KX-2GP  [C805H54]  139.99 100.42 270 bottom
C2601  SC10U6D3V3MX-GP  [C603H38]  64.47 37.26 180 top
C2602  SCD1U16V2KX-3GP  [C402H22]  65.69 36.26 180 top
C2603  SC2200P50V2KX-2GP  [C402H22]  137.45 70.83 90 bottom
C2604  SC4D7U6D3V3KX-GP  [C603H36]  139.48 69.31 270 bottom
C2605  SCD1U10V2KX-5GP  [C402H22]  137.45 69.94 90 bottom
C2606  SC470P50V3JN-2GP  [C603H36]  101.12 103.6 0 bottom
C2607  SC2200P50V2KX-2GP  [C402H22]  72.42 38.45 0 top
C2608  SCD1U16V2KX-3GP  [C402H22]  67.98 43.78 270 top
C2609  SCD1U16V2KX-3GP  [C402H22]  69.76 43.53 90 top
C2610  SCD1U16V2KX-3GP  [C402H22]  100.74 27.15 0 bottom
C2612  SCD1U16V2KX-3GP  [C402H22]  81.69 36.04 270 top
C2613  SC100P50V2JN-3GP  [C402H22]  77.25 36.67 180 top
C2701  SCD47U10V2KX-GP  [C402H22]  25.05 19.53 180 top
C2706  SC4D7U6D3V3KX-GP  [C603H36]  23.65 31.97 180 top
C2707  SCD1U16V2KX-3GP  [C402H22]  28.1 27.15 90 top
C2708  SC4D7U6D3V3KX-GP  [C603H36]  25.31 31.97 180 top
C2709  SCD1U16V2KX-3GP  [C402H22]  25.43 29.18 90 top
C2710  SC2D2U10V3KX-1GP  [C603H36]  29.62 27.02 0 top
C2711  SCD1U16V2KX-3GP  [C402H22]  22.51 31.59 180 top
C2712  SCD1U16V2KX-3GP  [C402H22]  22.77 19.53 0 top
C2713  SCD1U16V2KX-3GP  [C402H22]  15.91 24.22 270 top
C2714  SC1KP50V2KX-1GP  [C402H22]  27.97 21.81 90 top
C2715  SC2D2U10V3KX-1GP  [C603H36]  18.7 30.57 270 top
C2720  SCD1U16V2KX-3GP  [C402H22]  20.91 18.69 180 top
C2721  SC1U10V2KX-1GP  [C402H22]  28.28 23.06 0 top
C2722  SC1U10V2KX-1GP  [C402H22]  27.21 32.73 270 top
C2723  SC22P50V2JN-4GP  [C402H22]  25.94 19.53 180 top
C2724  SC2D2U10V3KX-1GP  [C603H36]  20.48 27.55 90 bottom
C2725  SC2D2U10V3KX-1GP  [C603H36]  19.97 26.28 90 bottom
C2726  SC2D2U10V3KX-1GP  [C603H36]  23.91 19.14 0 top
C2727  SCD1U16V2KX-3GP  [C402H22]  20.99 30.96 90 top
C2728  SC2D2U10V3KX-1GP  [C603H36]  20.86 32.61 180 top
C2729  SC1U10V2KX-1GP  [C402H22]  21.88 19.53 180 top
C2730  SC1U10V2KX-1GP  [C402H22]  15.78 26.26 270 bottom
C2901  SC1U6D3V2KX-GP  [C402H22]  27.59 30.19 180 bottom
C2902  SC10U10V3MX-GP  [C603H36]  18.45 33.5 270 top
C2903  SC10U10V3MX-GP  [C603H36]  16.92 21.81 0 bottom
C2907  SC10U10V3MX-GP  [C603H36]  15.53 21.68 180 top
C2908  SC10U10V3MX-GP  [C603H36]  18.14 19.5 180 top
C3401  SC1U6D3V2KX-GP  [C402H22]  16.29 67.91 0 bottom
C3402  SCD1U10V2KX-5GP  [C402H22]  24.29 50.77 270 top
C3403  SCD1U10V2KX-5GP  [C402H22]  15.27 67.91 0 bottom
C3404  SC100U6D3V6MX-GP  [C1206H71]  17.81 67.61 0 bottom
C3502  SCD1U16V2KX-3GP  [C402H22]  24.29 49.88 270 top
C3507  SCD1U16V2KX-3GP  [C402H22]  16.92 50.39 0 bottom
C3508  SC1U10V2KX-1GP  [C402H22]  16.03 50.39 0 bottom
C3512  SC22U6D3V5MX-2GP  [C805H58]  18.32 51.02 0 bottom
C3513  SC22U6D3V5MX-2GP  [C805H58]  16.54 48.1 180 bottom
C3601  SCD1U10V2KX-5GP  [C402H22]  20.86 63.59 90 bottom
C3602  SCD1U10V2KX-5GP  [C402H22]  20.86 64.48 90 bottom
C3603  SCD1U10V2KX-5GP  [C402H22]  21.75 45.56 90 bottom
C3604  SCD1U10V2KX-5GP  [C402H22]  21.75 46.45 90 bottom
C4001  SC470P50V2KX-3GP  [C402H22]  28.23 94.2 270 top
C4002  SC470P50V2KX-3GP  [C402H22]  31.78 94.96 180 top
C4004  SC10U10V5KX-2GP  [C805H54]  35.72 91.94 180 bottom
C4005  SC10U10V5KX-2GP  [C805H54]  25.06 91.92 90 bottom
C4006  SC10U6D3V3MX-GP  [C603H38]  62.7 94.09 270 top
C4007  SCD1U16V2KX-3GP  [C402H22]  68.84 92.6 180 top
C4008  SCD1U16V2KX-3GP  [C402H22]  70.42 70.4 270 top
C4009  SC10U6D3V3MX-GP  [C603H38]  135.92 29.94 90 bottom
C4012  SC10U6D3V3MX-GP  [C603H38]  64.52 80.79 180 bottom
C4013  SC10U10V5KX-2GP  [C805H54]  60.08 82.92 180 bottom
C4014  SCD1U16V2KX-3GP  [C402H22]  65.06 74.64 270 bottom
C4015  SCD1U16V2KX-3GP  [C402H22]  38.01 86.53 90 top
C4016  SCD1U16V2KX-3GP  [C402H22]  61.42 92.59 180 top
C4017  SCD1U16V2KX-3GP  [C402H22]  65.37 84.22 0 bottom
C4022  SC1U10V2KX-1GP  [C402H22]  20.73 33.37 90 bottom
C4026  SCD1U16V2KX-3GP  [C402H22]  21.37 34.64 0 bottom
C4027  SCD1U16V2KX-3GP  [C402H22]  26.45 33.75 180 bottom
C4031  SC1U10V2KX-1GP  [C402H22]  63.84 85.46 90 top
C4032  SC1U10V2KX-1GP  [C402H22]  64.18 88.89 90 top
C4033  SC1U10V2KX-1GP  [C402H22]  61.42 90.91 0 top
C4034  SC1U10V2KX-1GP  [C402H22]  62.44 79.42 90 bottom
C4101  SC1U10V2KX-1GP  [C402H22]  77.86 105.07 180 top
C4102  SC1U10V2KX-1GP  [C402H22]  75.72 112.49 90 top
C4201  SCD022U16V2KX-3GP  [C402H22]  138.21 64.99 0 bottom
C4202  SCD022U16V2KX-3GP  [C402H22]  120.81 33.88 180 top
C5501  SCD1U10V2KX-5GP  [C402H22]  61.37 90.65 180 bottom
C5502  SC4D7U6D3V3KX-L-GP  [C603H36]  34.07 91.66 180 bottom
C5503  SC4D7U6D3V3KX-GP  [C603H36]  41.43 91.66 180 bottom
C5504  SCD1U10V2KX-5GP  [C402H22]  60.48 90.65 180 bottom
C5505  SC4D7U6D3V3KX-L-GP  [C603H36]  46.13 99.92 180 top
C5506  SCD1U10V2KX-5GP  [C402H22]  59.6 90.65 180 bottom
C5507  SCD1U10V2KX-L1-GP  [C402H22]  44.99 100.17 180 top
C5508  SC1U6D3V2KX-L-1-GP  [C402H22]  44.1 100.17 0 top
C5509  SCD1U10V2KX-5GP  [C402H22]  58.71 90.65 180 bottom
C5510  SCD1U10V2KX-5GP  [C402H22]  57.82 90.65 180 bottom
C5511  SCD1U10V2KX-5GP  [C402H22]  56.93 90.65 180 bottom
C5512  SCD1U50V3KX-L-GP  [C603H36]  66.43 94.84 90 top
C5513  SC1KP50V2KX-L-1-GP  [C402H22]  66.78 93.8 90 top
C5514  SC4D7U25V5KX-L2-GP  [C805H58]  63.03 90.97 180 bottom
C5515  SC4D7U6D3V3KX-GP  [C603H36]  28.61 91.79 90 bottom
C5516  SCD1U50V3KX-L-GP  [C603H36]  29.88 95.34 90 top
C5517  SC4D7U25V5KX-L2-GP  [C805H58]  25.69 95.6 90 bottom
C5701  SCD1U10V2KX-5GP  [C402H22]  16.54 85.21 90 top
C5702  SCD1U10V2KX-5GP  [C402H22]  18.8 84.17 90 bottom
C5703  SCD1U10V2KX-5GP  [C402H22]  20.4 76.52 90 bottom
C5704  SCD1U10V2KX-5GP  [C402H22]  17.63 77.92 0 top
C5705  SCD1U10V2KX-5GP  [C402H22]  12.61 75.02 0 bottom
C5706  SCD1U10V2KX-5GP  [C402H22]  13.49 75.02 0 bottom
C5707  SCD1U16V2KX-3GP  [C402H22]  20.38 79.09 90 bottom
C5708  SCD1U16V2KX-3GP  [C402H22]  20.48 83.53 90 bottom
C5709  SCD1U16V2KX-3GP  [C402H22]  20.38 78.25 90 bottom
C5710  SCD1U16V2KX-3GP  [C402H22]  20.38 79.98 90 bottom
C5711  SCD1U16V2KX-3GP  [C402H22]  20.48 82.64 90 bottom
C5712  SCD1U16V2KX-3GP  [C402H22]  20.48 80.87 90 bottom
C5713  SCD1U16V2KX-3GP  [C402H22]  15.01 91.26 180 top
C5714  SCD1U16V2KX-3GP  [C402H22]  20.38 77.36 90 bottom
C5715  SCD1U16V2KX-3GP  [C402H22]  20.48 81.76 90 bottom
C5716  SCD1U10V2KX-5GP  [C402H22]  13.21 84.19 270 bottom
C6001  SCD01U50V2KX-1GP  [C402H22]  119.67 28.8 270 bottom
C6002  SCD1U16V2KX-3GP  [C402H22]  133.61 29.13 270 bottom
C6003  SCD01U50V2KX-1GP  [C402H22]  119.67 27.91 270 bottom
C6004  SC2D2U10V3KX-1GP  [C603H36]  133.53 30.17 270 bottom
C6005  SCD01U50V2KX-1GP  [C402H22]  118.88 26.13 270 bottom
C6006  SCD01U50V2KX-1GP  [C402H22]  118.88 27.02 270 bottom
C6501  SCD1U16V2KX-3GP  [C402H22]  24.67 14.32 90 bottom
C6502  SCD1U16V2KX-3GP  [C402H22]  99.98 25.24 180 bottom
C6503  SCD1U16V2KX-3GP  [C402H22]  116.62 25.37 90 top
C6901  SC1U10V2KX-1GP  [C402H22]  84.49 109.19 0 top
C6902  SCD1U10V2KX-5GP  [C402H22]  95.54 106.14 90 top
C6903  SCD01U50V2KX-1GP  [C402H22]  84.49 102.58 180 top
C6904  SCD01U50V2KX-1GP  [C402H22]  91.98 100.55 270 top
C6905  SCD01U50V2KX-1GP  [C402H22]  92.87 99.66 270 top
C6906  SCD1U10V2KX-5GP  [C402H22]  95.54 102.58 90 top
C6907  SCD1U10V2KX-5GP  [C402H22]  94.77 107.66 180 top
C6908  SC15P50V2JN-2-GP  [C402H22]  95.54 105.12 90 top
C6909  SC15P50V2JN-2-GP  [C402H22]  95.54 103.47 90 top
C7001  SCD047U16V2KX-1-GP  [C402H22]  15.15 71.85 0 top
C7002  SCD1U16V2KX-3GP  [C402H22]  11.72 72.74 0 bottom
C7003  SCD1U10V2KX-5GP  [C402H22]  162.34 16.99 0 top
C7004  SC10U6D3V3MX-L-GP  [C603H38]  160.64 17.37 270 top
C7006  SCD1U16V2KX-3GP  [C402H22]  156.62 16.48 90 top
C7007  SC10U6D3V3MX-GP  [C603H38]  157.26 21.68 90 top
C9901  SCD1U16V2KX-3GP  [C402H22]  107.12 29.18 0 top
C9902  SCD1U16V2KX-3GP  [C402H22]  104.44 41.31 180 top
C9903  SCD1U16V2KX-3GP  [C402H22]  109.63 29.18 180 top
C9904  SCD1U16V2KX-3GP  [C402H22]  105.7 41.28 90 top
C9905  SCD1U16V2KX-3GP  [C402H22]  108.74 41.37 180 top
CPU1  SKYLAKE-U-GP  [BGA1356M4224-U2H52]  80.9 63.5 90 bottom
D401  RB751V-40H-GP  [SOD323AKH38]  102.33 82.6 270 top
D2402  RB751V-40H-GP  [SOD323AKH38]  139.86 73.88 90 top
D2403  RB751V-40H-GP  [SOD323AKH38]  158.91 59.4 180 top
D2404  RB751V-40H-GP  [SOD323AKH38]  162.37 34.89 270 top
D2501  BAS40C-2-GP  [SOT-23-9H44]  140.67 64.86 270 bottom
D2601  RB551V30-1-GP  [SOD323AKH44]  138.31 69.06 90 top
D2701  BAT54C-7-F-3-GP  [SOT23-2D4-312H48]  29.12 33.62 0 bottom
D4001  BAS16PT-GP  [SOT-23-13H46]  135.69 33.42 270 bottom
D4002  BAS16-6-GP  [SOT23-2D4-312H44]  48.9 90.93 90 bottom
D4301  DA3X101F0L-1-GP  [SOT23-2D8-312H56]  96.04 26.26 0 bottom
D4302  DA3X101F0L-1-GP  [SOT23-2D8-312H56]  92.49 26.26 0 bottom
D4303  DA3X101F0L-1-GP  [SOT23-2D8-312H56]  88.93 26.26 0 bottom
D5501  BAT54C-7-F-3-GP  [SOT23-2D4-312H48]  73.49 97.38 90 top
D5502  BAT54C-7-F-3-GP  [SOT23-2D4-312H48]  68.32 97.5 270 top
D5701  BAW56-9-GP  [SOT-23-10H44]  16.87 87.7 270 top
D7001  BAT54A-7-F-2-GP  [SOT23-2D4-312H48]  146.92 35.78 180 bottom
DB1  DM-FOX-CON10-S1-GP-01  [DM-HS81100-01]  104.55 113.63 0 bottom
DB3  ACES-CON6-58-GP  [50696-00601-001]  127.54 17.11 180 bottom
DCIN1  ACES-CON8-13-GP-U1  [50224-0080N-W02]  17.6 91.5 0 bottom
DIMM1  DDR3-204P-215-GP-U  [DS2RK-20401-TP4B-U]  125.8 66 270 bottom
EC401  AZ5725-01FDR7G-GP  [SOD882-10D6-1H20]  63.79 43.66 180 bottom
EC1001  SCD1U25V2KX-L-GP  [C402H22]  47.4 66.01 270 top
EC1002  SCD1U25V2KX-L-GP  [C402H22]  67.72 67.66 180 top
EC1003  SCD1U25V2KX-L-GP  [C402H22]  68.61 67.66 180 top
EC1004  SCD1U25V2KX-L-GP  [C402H22]  55.79 78.83 180 top
EC1005  SCD1U25V2KX-L-GP  [C402H22]  57.56 78.83 180 top
EC1006  SC1U10V2KX-1GP  [C402H22]  76.44 56.94 0 top
EC1007  SCD1U25V2KX-L-GP  [C402H22]  74.96 45.18 270 top
EC1701  AZ5725-01FDR7G-GP  [SOD882-10D6-1H20]  66.71 39.59 180 bottom
EC1702  AZ5725-01FDR7G-GP  [SOD882-10D6-1H20]  67.65 80.61 90 top
EC1703  AZ5725-01FDR7G-GP  [SOD882-10D6-1H20]  98.71 88.11 0 top
EC1704  AZ5725-01FDR7G-GP  [SOD882-10D6-1H20]  103.66 74.64 0 top
EC1705  AZ5725-01FDR7G-GP  [SOD882-10D6-1H20]  104.3 72.23 180 top
EC1706  SC1KP50V2KX-1GP  [C402H22]  67.72 82.64 0 top
EC1707  SCD1U16V2KX-3GP  [C402H22]  163.48 36.42 90 top
EC1708  AZ5725-01FDR7G-GP  [SOD882-10D6-1H20]  61.25 39.97 270 top
EC1709  AZ5725-01FDR7G-GP  [SOD882-10D6-1H20]  61.25 42.13 0 top
EC1711  AZ5725-01FDR7G-GP  [SOD882-10D6-1H20]  101.85 72.43 90 top
EC1712  SCD1U16V2KX-3GP  [C402H22]  112.05 98.39 270 top
EC1801  SC10P50V2JN-4GP  [C402H22]  98.33 81.63 90 top
EC1802  SC10P50V2JN-4GP  [C402H22]  98.33 80.74 90 top
EC1803  SC4D7P50V2BN-GP  [C402H22]  92.56 71.65 90 top
EC1806  SCD1U16V2KX-3GP  [C402H22]  105.06 87.98 270 top
EC1807  SCD1U16V2KX-3GP  [C402H22]  102.01 87.72 90 top
EC1808  SCD1U16V2KX-3GP  [C402H22]  108.74 97.12 180 top
EC1901  SC10P50V2JN-4GP  [C402H22]  99.35 68.55 270 top
EC1902  SCD1U16V2KX-3GP  [C402H22]  99.35 69.44 90 top
EC2101  SCD1U25V2KX-L-GP  [C402H22]  70.01 93.44 180 top
EC2501  SC4D7P50V2BN-GP  [C402H22]  125.89 106.14 90 top
EC2502  SC4D7P50V2BN-GP  [C402H22]  127.41 103.73 270 top
EC2503  SC10P50V2JN-4GP  [C402H22]  126.78 107.16 270 top
EC2504  SC4D7P50V2BN-GP  [C402H22]  138.08 86.84 180 bottom
EC2505  SC10P50V2JN-4GP  [C402H22]  136.3 100.3 0 bottom
EC2506  SC4D7P50V2BN-GP  [C402H22]  134.53 100.3 0 bottom
EC2701  SC10P50V2JN-4GP  [C402H22]  27.59 25.62 90 top
EC2703  SCD1U25V2KX-GP  [C402H22]  19.84 37.31 0 bottom
EC2704  SC1KP50V2KX-1GP  [C402H22]  22 22.45 270 bottom
EC2705  SCD1U25V2KX-GP  [C402H22]  18.32 37.31 0 bottom
EC2706  SC1KP50V2KX-1GP  [C402H22]  19.84 16.6 180 bottom
EC2707  SC1KP50V2KX-1GP  [C402H22]  19.84 25.24 270 bottom
EC2708  SCD1U16V2KX-3GP  [C402H22]  29.75 20.77 90 top
EC2709  SCD1U16V2KX-3GP  [C402H22]  26.83 17.75 0 top
EC2901  SC1KP50V2KX-1GP  [C402H22]  15.65 16.99 270 bottom
EC2902  SC1KP50V2KX-1GP  [C402H22]  17.08 13.48 270 bottom
EC2903  SC1KP50V2KX-1GP  [C402H22]  15.65 5.68 90 top
EC2904  SC1KP50V2KX-1GP  [C402H22]  15.15 9.62 180 top
EC2905  SC100P50V2JN-3GP  [C402H22]  15.53 23.84 0 bottom
EC2906  SC100P50V2JN-3GP  [C402H22]  16.42 33.62 270 top
EC2907  SC100P50V2JN-3GP  [C402H22]  20.76 19.7 0 bottom
EC2908  SC100P50V2JN-3GP  [C402H22]  16.29 31.97 180 bottom
EC4001  SCD1U16V2KX-3GP  [C402H22]  62.03 78.15 0 bottom
EC4301  SC10U25V3MX-GP  [C603H40]  20.99 89.1 180 top
EC4302  SC1KP50V2KX-1GP  [C402H22]  19.84 88.97 180 top
EC4303  SCD1U50V3KX-GP  [C603H36]  85.91 27.63 270 bottom
EC4304  SCD1U25V2KX-GP  [C402H22]  88.25 23.21 270 bottom
EC4305  SC10P50V2JN-4GP  [C402H22]  89.31 28.67 270 bottom
EC4306  SC10P50V2JN-4GP  [C402H22]  92.41 28.67 270 bottom
EC4307  SC10P50V2JN-4GP  [C402H22]  98.33 26.76 0 bottom
EC5501  SC6D8P50V2DN-GP  [C402H22]  50.58 96.61 270 top
EC5502  SCD1U25V2KX-GP  [C402H22]  42.58 91.92 180 bottom
EC5503  SC22P50V2JN-4GP  [C402H22]  54.26 102.08 270 top
EC5504  SC22P50V2JN-4GP  [C402H22]  56.04 102.08 90 top
EC5505  SC33P50V2JN-3GP  [C402H22]  28.73 92.93 90 bottom
EC6501  SC33P50V2JN-3GP  [C402H22]  111.92 23.46 90 top
EC6502  SC33P50V2JN-3GP  [C402H22]  109.89 23.46 270 top
EC6503  SC33P50V2JN-3GP  [C402H22]  122.71 24.48 90 top
EC6504  SC33P50V2JN-3GP  [C402H22]  122.71 26 90 top
EC6601  SC33P50V2JN-3GP  [C402H22]  160.94 36.42 90 top
EC6602  SC33P50V2JN-3GP  [C402H22]  149.81 65.23 0 top
EC6603  SC33P50V2JN-3GP  [C402H22]  150.67 65.22 0 top
EC8901  SCD1U25V2KX-GP  [C402H22]  22.26 19.91 270 bottom
EC8902  SC1KP50V2KX-1GP  [C402H22]  20.86 28.59 270 bottom
EC8903  SCD1U25V2KX-GP  [C402H22]  22.13 36.04 90 top
EC8904  SC1KP50V2KX-1GP  [C402H22]  19.84 16.6 0 top
EC8905  SC1U25V3KX-1-GP  [C603H36]  45.88 31.72 0 top
EC8906  SC2200P50V2KX-2GP  [C402H22]  41.94 83.41 90 top
EC8907  SCD1U25V2KX-GP  [C402H22]  37.75 76.17 270 top
EC8908  SCD1U25V2KX-GP  [C402H22]  43.72 70.45 90 top
EC8909  SCD1U25V2KX-GP  [C402H22]  69.07 87.39 180 bottom
EC8910  SCD1U25V2KX-GP  [C402H22]  120.3 97.12 270 top
EC8911  SCD1U25V2KX-GP  [C402H22]  36.74 91.92 0 top
EC8912  SCD1U25V2KX-GP  [C402H22]  35.85 90.65 180 top
EC8913  SCD1U25V2KX-GP  [C402H22]  23.78 55.97 90 top
EC8914  SCD1U25V2KX-GP  [C402H22]  136.81 82.52 180 bottom
EC8915  SCD1U25V2KX-GP  [C402H22]  29.12 84.68 90 top
EC8916  SCD1U25V2KX-GP  [C402H22]  138.08 58.64 90 top
EC8917  SCD1U25V2KX-GP  [C402H22]  27.08 18.13 90 bottom
EC8918  SC1KP50V2KX-1GP  [C402H22]  91.35 51.78 0 top
EC8919  SCD1U25V2KX-GP  [C402H22]  101.38 51.78 0 top
EC8920  SCD1U25V2KX-GP  [C402H22]  107.09 51.91 0 top
EC8921  SCD1U25V2KX-GP  [C402H22]  111.16 51.78 0 top
EC8922  SCD1U25V2KX-GP  [C402H22]  119.03 51.91 0 top
EC8923  SCD1U25V3KX-GP  [C603H36]  103.66 51.78 0 top
EC8924  SCD1U25V3KX-GP  [C603H36]  114.21 51.78 0 top
EC8925  SCD1U25V3KX-GP  [C603H36]  116.24 73.75 180 top
EC8926  SC1U25V3KX-1-GP  [C603H36]  28.23 71.85 270 top
EC8927  SC1U25V3KX-1-GP  [C603H36]  46.9 47.85 90 top
EC8928  SC1U25V3KX-1-GP  [C603H36]  55.02 37.81 180 top
EC8929  SC1U25V3KX-1-GP  [C603H36]  52.74 29.3 0 top
EC8930  SC1U25V3KX-1-GP  [C603H36]  71.66 29.69 90 top
EC8931  SC1U25V3KX-1-GP  [C603H36]  93.5 25.37 270 top
EC8932  SC1U25V3KX-1-GP  [C603H36]  109.63 19.14 90 top
EC8933  SC2200P50V2KX-2GP  [C402H22]  86.85 71.19 180 top
EC8934  SC2200P50V2KX-2GP  [C402H22]  85.76 56.1 270 top
EC8935  SC2200P50V2KX-2GP  [C402H22]  85.76 53.69 270 top
EC8936  SCD1U25V2KX-GP  [C402H22]  110.9 73.75 180 top
EC8937  SCD1U25V2KX-GP  [C402H22]  113.82 73.75 180 top
EC8938  SCD1U25V2KX-GP  [C402H22]  118.78 73.75 180 top
ED501  AZ5725-01FDR7G-GP  [SOD882-10D6-1H20]  125.76 45.05 180 top
ED1217  AZ5725-01FDR7G-GP  [SOD882-10D6-1H20]  127.03 42.26 270 top
ED2901  AZ2025-01H-R7G-GP  [SOD-523-4H28]  16.42 37.05 180 bottom
ED2902  AZ2025-01H-R7G-GP  [SOD-523-4H28]  17.51 18.51 0 bottom
ED2903  AZ2025-01H-R7G-GP  [SOD-523-4H28]  15.7 19.02 0 bottom
ED2905  AZ2025-01H-R7G-GP  [SOD-523-4H28]  18.19 37.05 0 top
ED2906  AZ2025-01H-R7G-GP  [SOD-523-4H28]  20.1 37.05 0 top
EU3601  ESD3V3U4ULC-GP  [LGA9G2310H13]  15.91 62.96 270 bottom
EU3602  AZC099-04S-1-GP  [SOT-6H58]  17.18 58.77 270 bottom
EU3603  ESD3V3U4ULC-GP  [LGA9G2310H13]  16.8 44.93 270 bottom
EU3604  AZC099-04S-1-GP  [SOT-6H58]  18.19 40.61 270 bottom
F5501  POLYSW-1D1A24V-GP-U  [POLYSW-4633-UH43]  29.37 98.27 90 top
F5502  POLYSW-D5A6V-1-GP  [POLYSW-2114H50]  38.77 92.17 270 bottom
F5503  POLYSW-1D1A24V-GP-U  [POLYSW-4633-UH43]  63.32 97.94 270 top
F5504  POLYSW-1D1A6V-9-GP-U  [POLYSW-2114H30]  31.53 90.98 90 bottom
F5701  POLYSW-1D1A6V-9-GP-U  [POLYSW-2114H30]  17.43 91.41 0 top
F6501  POLYSW-D5A6V-1-GP  [POLYSW-2114H50]  27.97 14.95 180 bottom
FAN1  ACES-CON4-29-GP  [50224-0040N-001]  140.8 78 0 bottom
G1801  GAP-OPEN  [CON2O-U]  102.16 86.55 270 top
H1  HOLE335R178-GP  [HOLE335R178]  21.8 101.5 180 bottom
H2  HOLE335R229-GP  [HOLE335R229]  9.6 17.5 180 bottom
H3  HOLE335R229-GP  [HOLE335R229]  74.8 18 180 bottom
H4  HOLE335R229-GP  [HOLE335R229]  145.8 20.5 180 bottom
H5  HOLE335R178-GP  [HOLE335R178]  138.8 106 180 bottom
H6  HOLE335R178-GP  [HOLE335R178]  68.3 104.5 180 bottom
HDA27  CX6008-11Z-GP  [QFN42J5-G3D6H36]  21.88 25.11 270 top
HDD1  FOX-CON20-1-GP-U1  [GS12201-1011-9H]  131.8 25 0 bottom
HDMI1  SKT-HDMI23-15-GP-U1  [SKT-HDMI23-178125-1]  2.3 83.1 90 bottom
HOMBD1  PSC-CON16-GP  [AYF531635]  31.8 99 270 bottom
HPMIC1  AUDIO-JK470-GP  [2SJ3095-013111F]  2.55 28.9 90 bottom
HS1  STF237R128H42-9-GP  [STF237R128H42]  57.9 60 180 bottom
HS2  STF237R128H42-9-GP  [STF237R128H42]  89.85 94.2 180 bottom
HS3  STF237R128H42-9-GP  [STF237R128H42]  89.85 32.8 180 bottom
IOBD1  ACES-CON50-7-GP  [50398-05071-001]  145.8 57 90 bottom
JTAG1  ACES-CON10-28-GP-U  [50675-01001-001]  131.71 19.35 0 top
KB1  ACES-CON26-13-GP-U  [50588-02601-001-U]  156.8 30.5 270 bottom
KBC24  MEC1404-NU-GP  [TQFP128-2H48]  152.56 47.47 270 top
KBLIT1  ACES-CON4-56-GP-U  [51575-00401-W01]  22.8 6.75 180 bottom
LCD1  ACES-CON40-11-GP-U  [50398-04071-001]  53.8 96 180 bottom
LIDSW1  S-5712ACDL1-M3T1U-GP  [SOT23-2D8-123H52]  5.85 73.2 0 bottom
NOREF  -  []  161 80.86 270 top
NOREF#2  *  [unnamed#2]  139.55 55.62 0 top
NOREF#3  -  []  -2 2 0 top
NOREF#4  -  []  -2 2 0 top
NOREF#5  *  [unnamed#2]  166.52 151.59 0 top
NOREF#6  -  []  -2 2 0 top
NOREF#7  *  [unnamed#2]  163.86 12.03 0 top
NOREF#8  -  [unnamed#2]  -5.04 144.5 0 top
NOREF#9  -  []  160.31 12.03 0 top
NOREF#10  -  []  -2 2 0 top
NOREF#11  -  [unnamed#2]  168.91 15.11 0 top
NOREF#12  -  [unnamed#2]  109.7 8.75 0 top
NOREF#13  -  [unnamed#2]  32.31 134.49 0 top
NOREF#14  -  [unnamed#2]  161.39 153.93 0 top
NOREF#15  *  [unnamed#2]  32.54 29.43 0 top
NOREF#16  -  [unnamed#2]  132 108.4 90 top
NOREF#17  *  [unnamed#2]  161.7 28.92 0 top
NOREF#18  -  []  -7.7 129.67 0 top
NOREF#19  -  [unnamed#2]  59.05 112 0 top
NOREF#20  -  []  107.86 59.91 0 top
NOREF#21  -  []  150.15 161.77 180 top
NOREF#22  *  [unnamed#2]  3.58 3.05 0 top
NOREF#23  -  [unnamed#2]  -4.55 14.32 0 top
NOREF#24  *  [unnamed#2]  15.91 16.1 0 top
NOREF#25  *  [unnamed#2]  -2.7 18.45 0 top
NOREF#26  -  [unnamed#2]  4 16.9 0 top
NOREF#27  -  []  67.85 3.52 0 top
NOREF#28  -  []  54.52 61.18 0 top
NOREF#29  *  [unnamed#2]  92.62 37.18 180 bottom
NOREF#30  -  []  161.2 59.53 180 bottom
NOREF#31  -  []  155.61 80.36 180 bottom
NOREF#32  *  [unnamed#2]  133.13 105.89 180 bottom
NOREF#33  -  []  164.75 70.58 180 bottom
NOREF#34  -  []  24.29 128.75 180 bottom
NOREF#35  -  []  160.18 11.4 180 bottom
NOREF#36  *  [unnamed#2]  3.58 3.05 180 bottom
NOREF#37  -  []  102.39 50.95 180 bottom
NOREF#38  *  [unnamed#2]  163.86 12.03 180 bottom
NOREF#39  -  []  81.44 92.8 180 bottom
NOREF#40  -  []  5.24 8.73 180 bottom
NOREF#41  *  [unnamed#2]  -2.7 18.45 180 bottom
NOREF#42  *  [unnamed#2]  70.11 94.41 180 bottom
NOREF#43  -  []  160.98 80.85 90 bottom
NOREF#44  *  [unnamed#2]  166.52 151.59 180 bottom
NOREF#45  -  []  98.71 62.58 180 bottom
PC1001  SC22U6D3V3MX-1-GP  [C603H40]  79.23 63.72 180 top
PC1002  SC22U6D3V3MX-1-GP  [C603H40]  77.91 63.72 180 top
PC1003  SC22U6D3V3MX-1-GP  [C603H40]  78.77 58.13 0 top
PC1004  SC22U6D3V3MX-1-GP  [C603H40]  76.61 63.72 180 top
PC1005  SC22U6D3V3MX-1-GP  [C603H40]  77.5 58.13 0 top
PC1006  SC22U6D3V3MX-1-GP  [C603H40]  80.55 63.72 180 top
PC1007  SC22U6D3V3MX-1-GP  [C603H40]  81.31 58.13 0 top
PC1008  SC22U6D3V3MX-1-GP  [C603H40]  82.58 58.13 0 top
PC1009  SC22U6D3V3MX-1-GP  [C603H40]  71.13 57.37 0 top
PC1010  SC22U6D3V3MX-1-GP  [C603H40]  80.04 58.13 0 top
PC1011  SC22U6D3V3MX-1-GP  [C603H40]  70.29 66.74 180 top
PC1012  SC22U6D3V3MX-1-GP  [C603H40]  49.82 69.06 180 top
PC1013  SC22U6D3V3MX-1-GP  [C603H40]  48.55 69.06 180 top
PC1014  SC22U6D3V3MX-1-GP  [C603H40]  68.49 57.8 0 top
PC1015  SC22U6D3V3MX-1-GP  [C603H40]  69.86 57.37 0 top
PC1016  SC22U6D3V3MX-1-GP  [C603H40]  65.82 59.2 270 top
PC1017  SC22U6D3V3MX-1-GP  [C603H40]  67.22 57.37 0 top
PC1018  SC22U6D3V3MX-1-GP  [C603H40]  65.82 60.47 270 top
PC1019  SC22U6D3V3MX-1-GP  [C603H40]  82.71 64.28 180 top
PC1020  SC22U6D3V3MX-1-GP  [C603H40]  57.31 71.21 180 top
PC1021  SC22U6D3V3MX-1-GP  [C603H40]  58.58 71.21 180 top
PC1022  SC22U6D3V3MX-1-GP  [C603H40]  59.85 71.21 180 top
PC1023  SC22U6D3V3MX-1-GP  [C603H40]  61.12 71.21 180 top
PC1024  SC22U6D3V3MX-1-GP  [C603H40]  62.39 71.21 180 top
PC1025  SC22U6D3V3MX-1-GP  [C603H40]  63.66 71.21 180 top
PC1026  SC22U6D3V3MX-1-GP  [C603H40]  61.37 64.23 0 top
PC1027  SC22U6D3V3MX-1-GP  [C603H40]  62.64 64.23 0 top
PC1028  SC22U6D3V3MX-1-GP  [C603H40]  63.91 64.23 0 top
PC1029  SC22U6D3V3MX-1-GP  [C603H40]  65.82 63.47 270 top
PC1030  SC22U6D3V3MX-1-GP  [C603H40]  65.82 61.74 270 top
PC1031  SC22U6D3V3MX-1-GP  [C603H40]  79.28 52.42 90 top
PC1032  SC22U6D3V3MX-1-GP  [C603H40]  53.5 53.94 180 top
PC1033  SC22U6D3V3MX-1-GP  [C603H40]  70.01 48.1 0 top
PC1034  SC22U6D3V3MX-1-GP  [C603H40]  80.68 40.86 0 top
PC1035  SC22U6D3V3MX-1-GP  [C603H40]  85.88 57.83 90 top
PC1036  SC22U6D3V3MX-1-GP  [C603H40]  82.58 67.02 270 top
PC1037  SC22U6D3V3MX-1-GP  [C603H40]  85.76 67.91 90 top
PC1038  SC22U6D3V3MX-1-GP  [C603H40]  84.72 72.99 90 top
PC1039  SC22U6D3V3MX-1-GP  [C603H40]  71.28 93.82 180 top
PC1041  SC22U6D3V3MX-1-GP  [C603H40]  63.79 54.32 180 top
PC1042  SC22U6D3V3MX-1-GP  [C603H40]  65.06 54.32 180 top
PC1043  SC22U6D3V3MX-1-GP  [C603H40]  74.71 44.04 270 top
PC1044  SC22U6D3V3MX-1-GP  [C603H40]  82.58 45.18 90 top
PC1045  SC22U6D3V3MX-1-GP  [C603H40]  56.29 78.45 0 bottom
PC1046  SC22U6D3V3MX-1-GP  [C603H40]  55.02 78.45 0 bottom
PC1047  SC22U6D3V3MX-1-GP  [C603H40]  53.63 79.47 0 bottom
PC1048  SC22U6D3V3MX-1-GP  [C603H40]  52.36 79.47 0 bottom
PC1049  SC22U6D3V3MX-1-GP  [C603H40]  51.09 79.47 0 bottom
